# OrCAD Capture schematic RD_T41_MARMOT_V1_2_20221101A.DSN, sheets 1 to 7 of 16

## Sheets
1 PAGE01_COVER: title: RD_T41_MARMOT; rev: V1.2
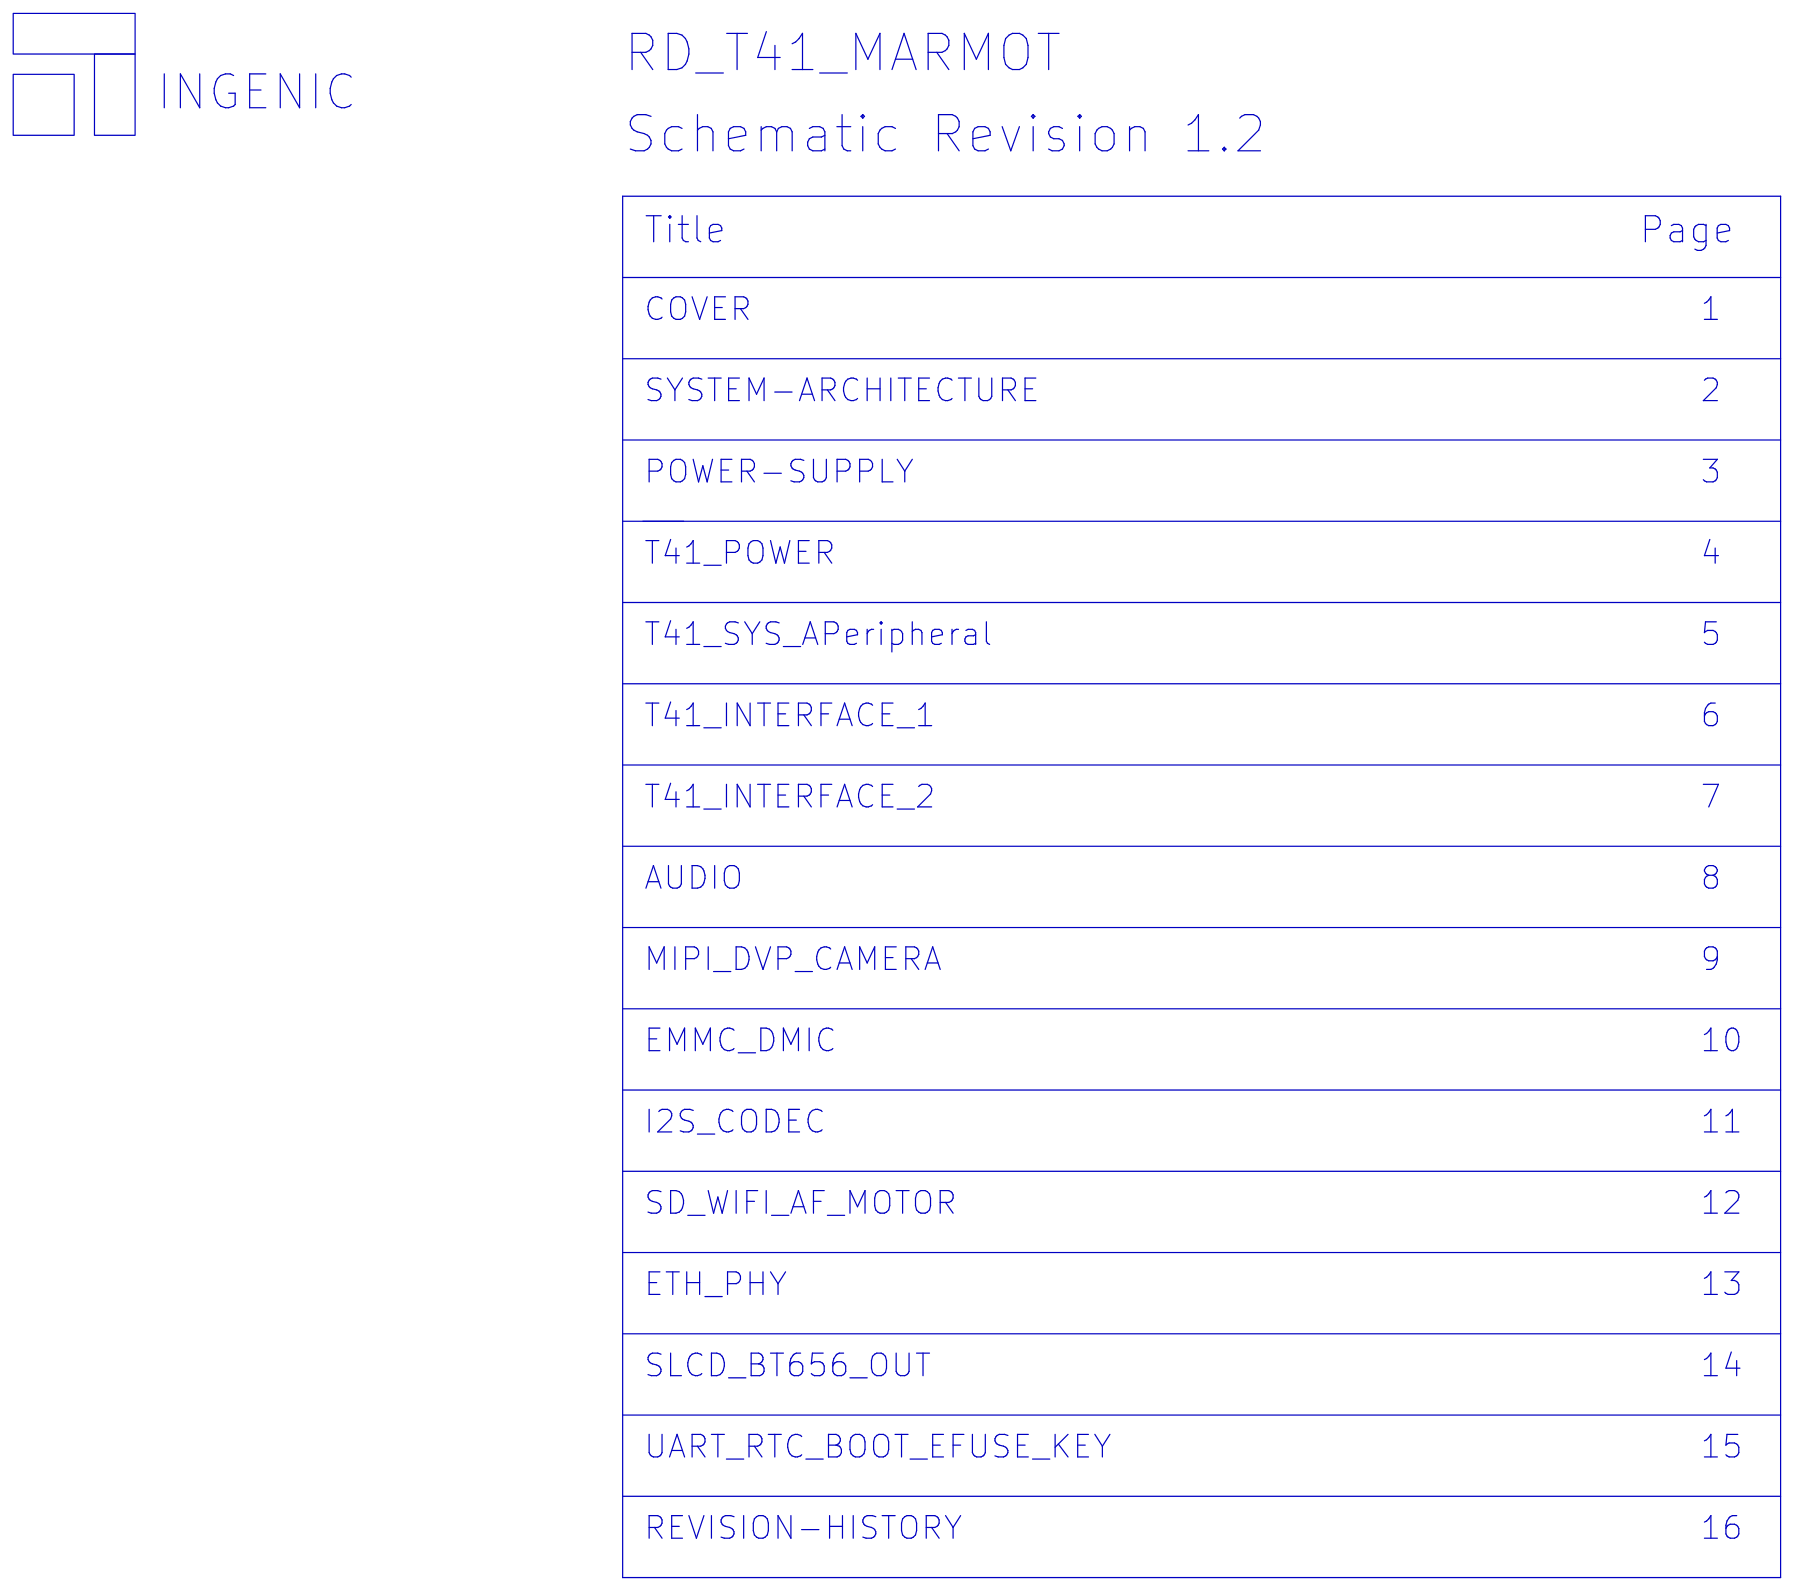
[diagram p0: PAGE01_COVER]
2 PAGE02_SYSTEM-ARCHITECT
3 PAGE03_POWER-SUPPLY: size A3
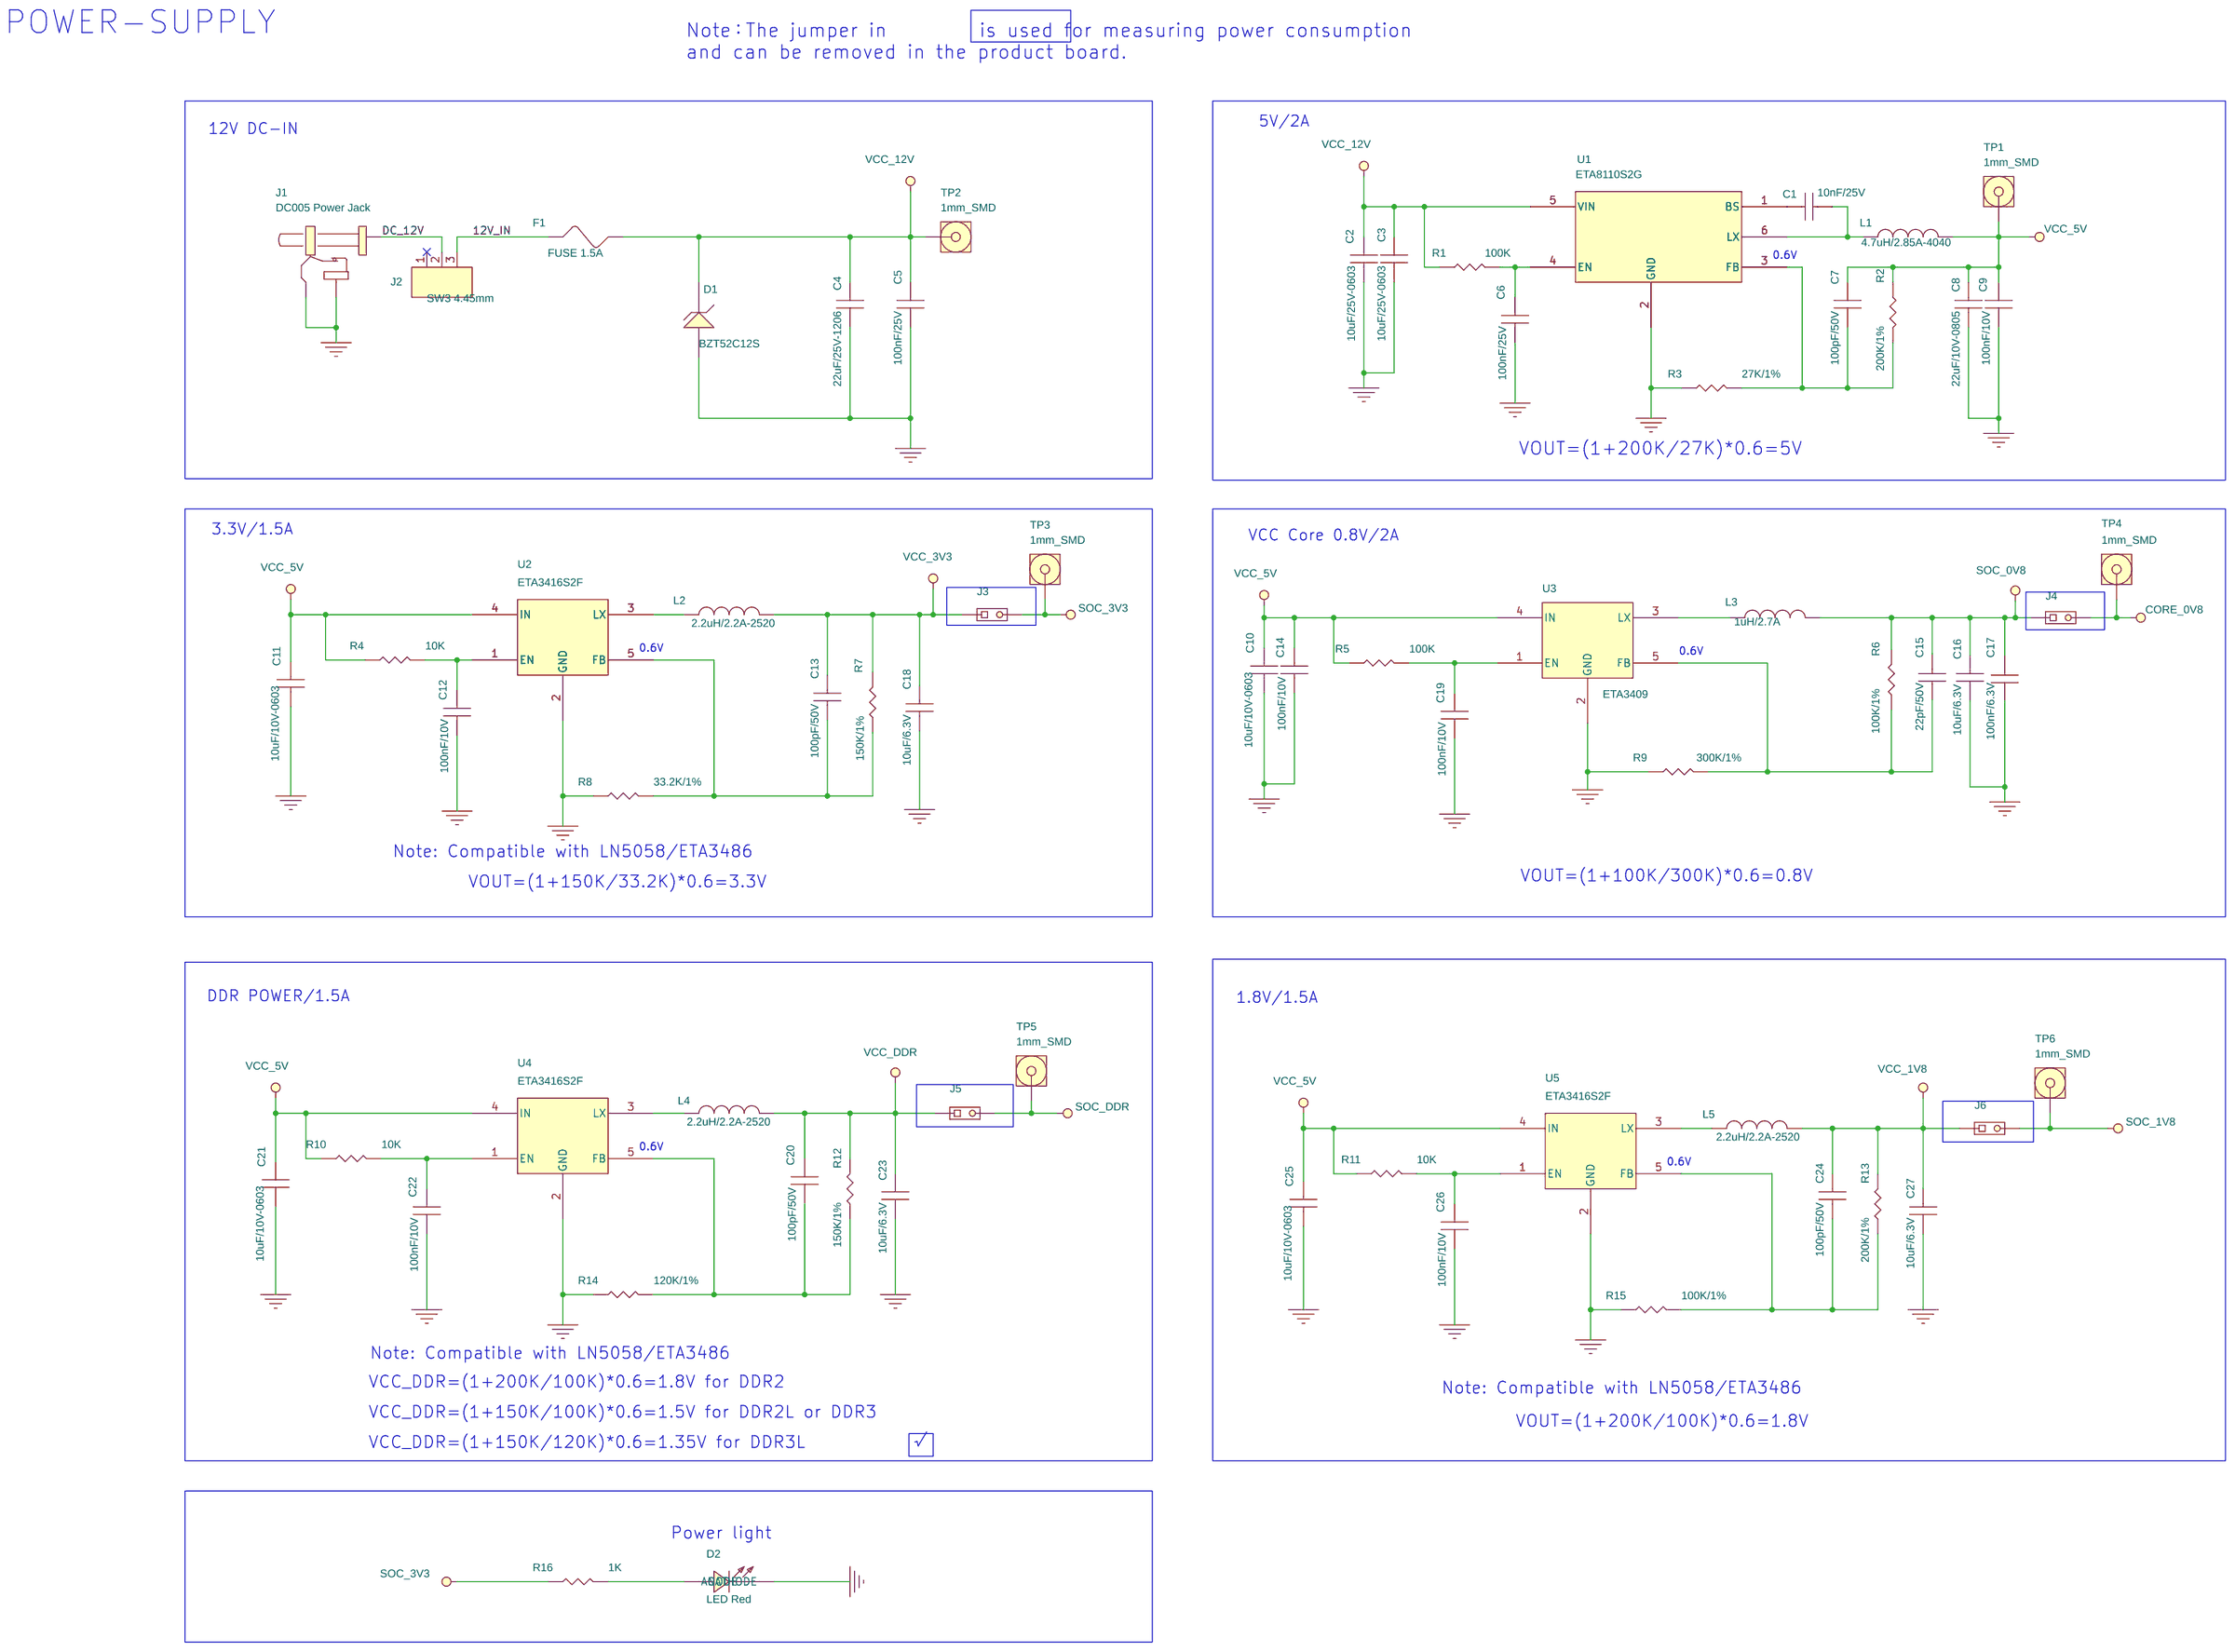
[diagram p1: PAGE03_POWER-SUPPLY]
4 PAGE04_T41_POWER: size A3
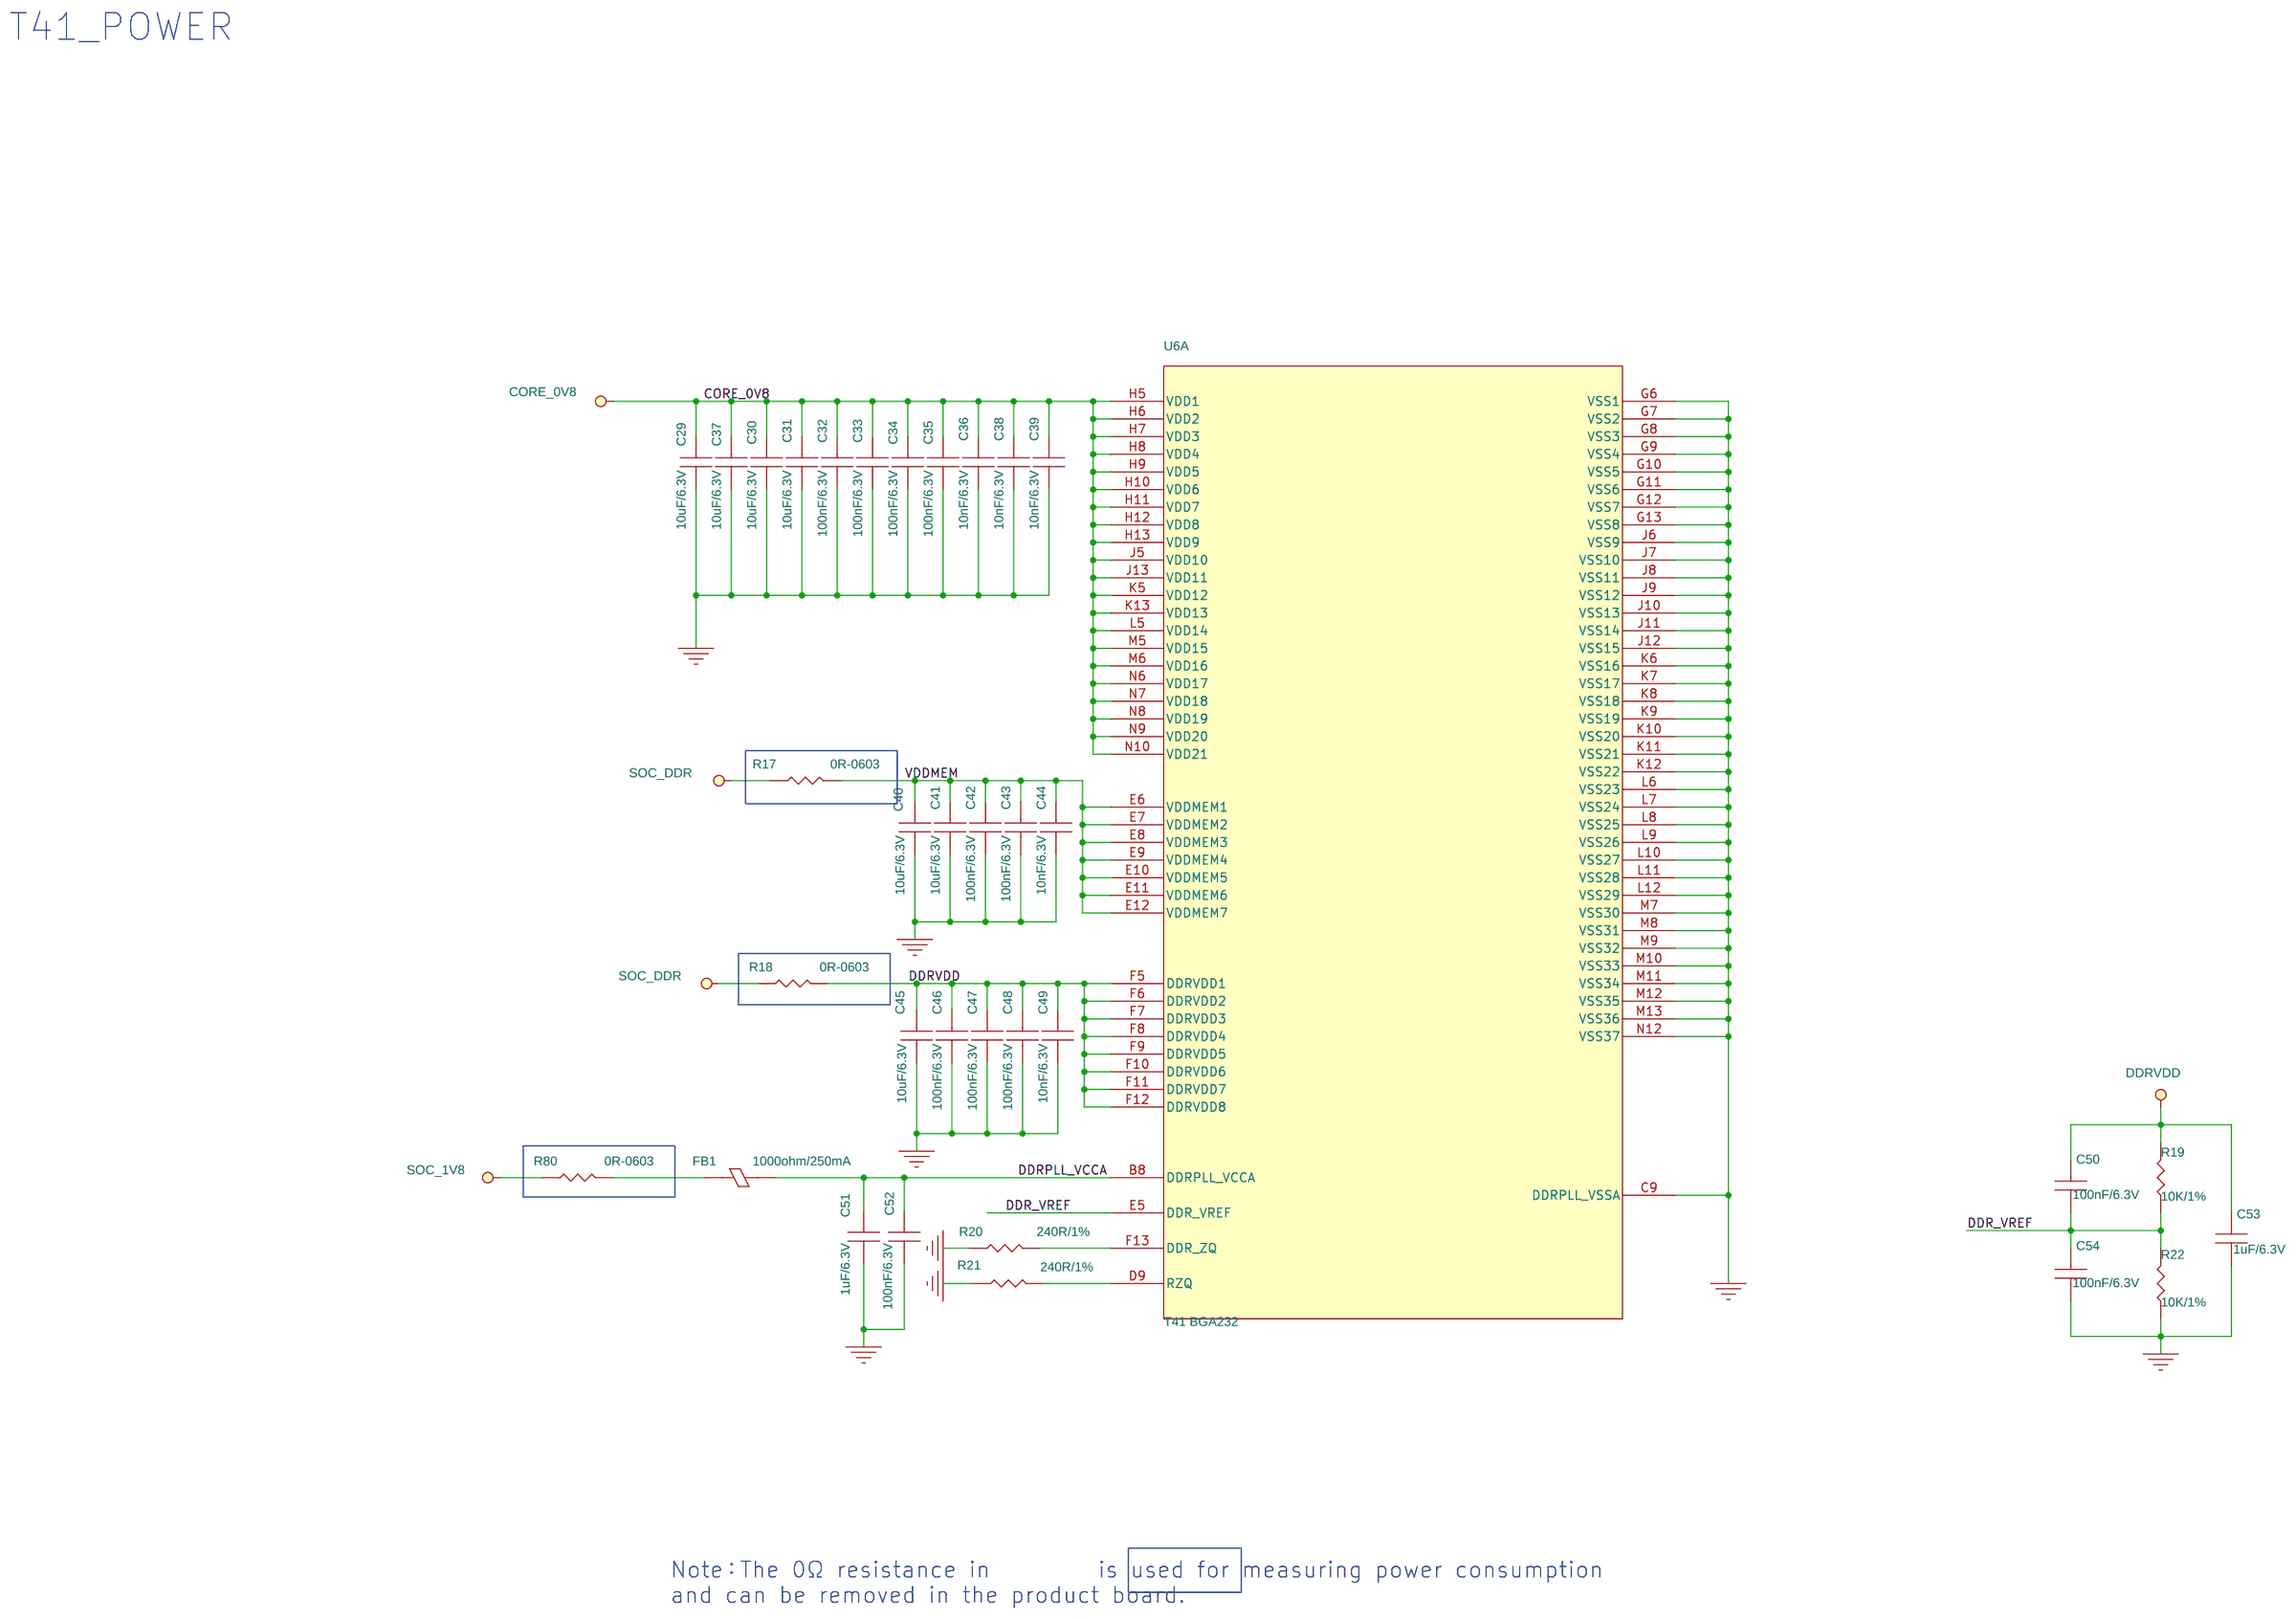
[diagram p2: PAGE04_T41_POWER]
5 PAGE05_T41_SYS_APeripheral: size A3
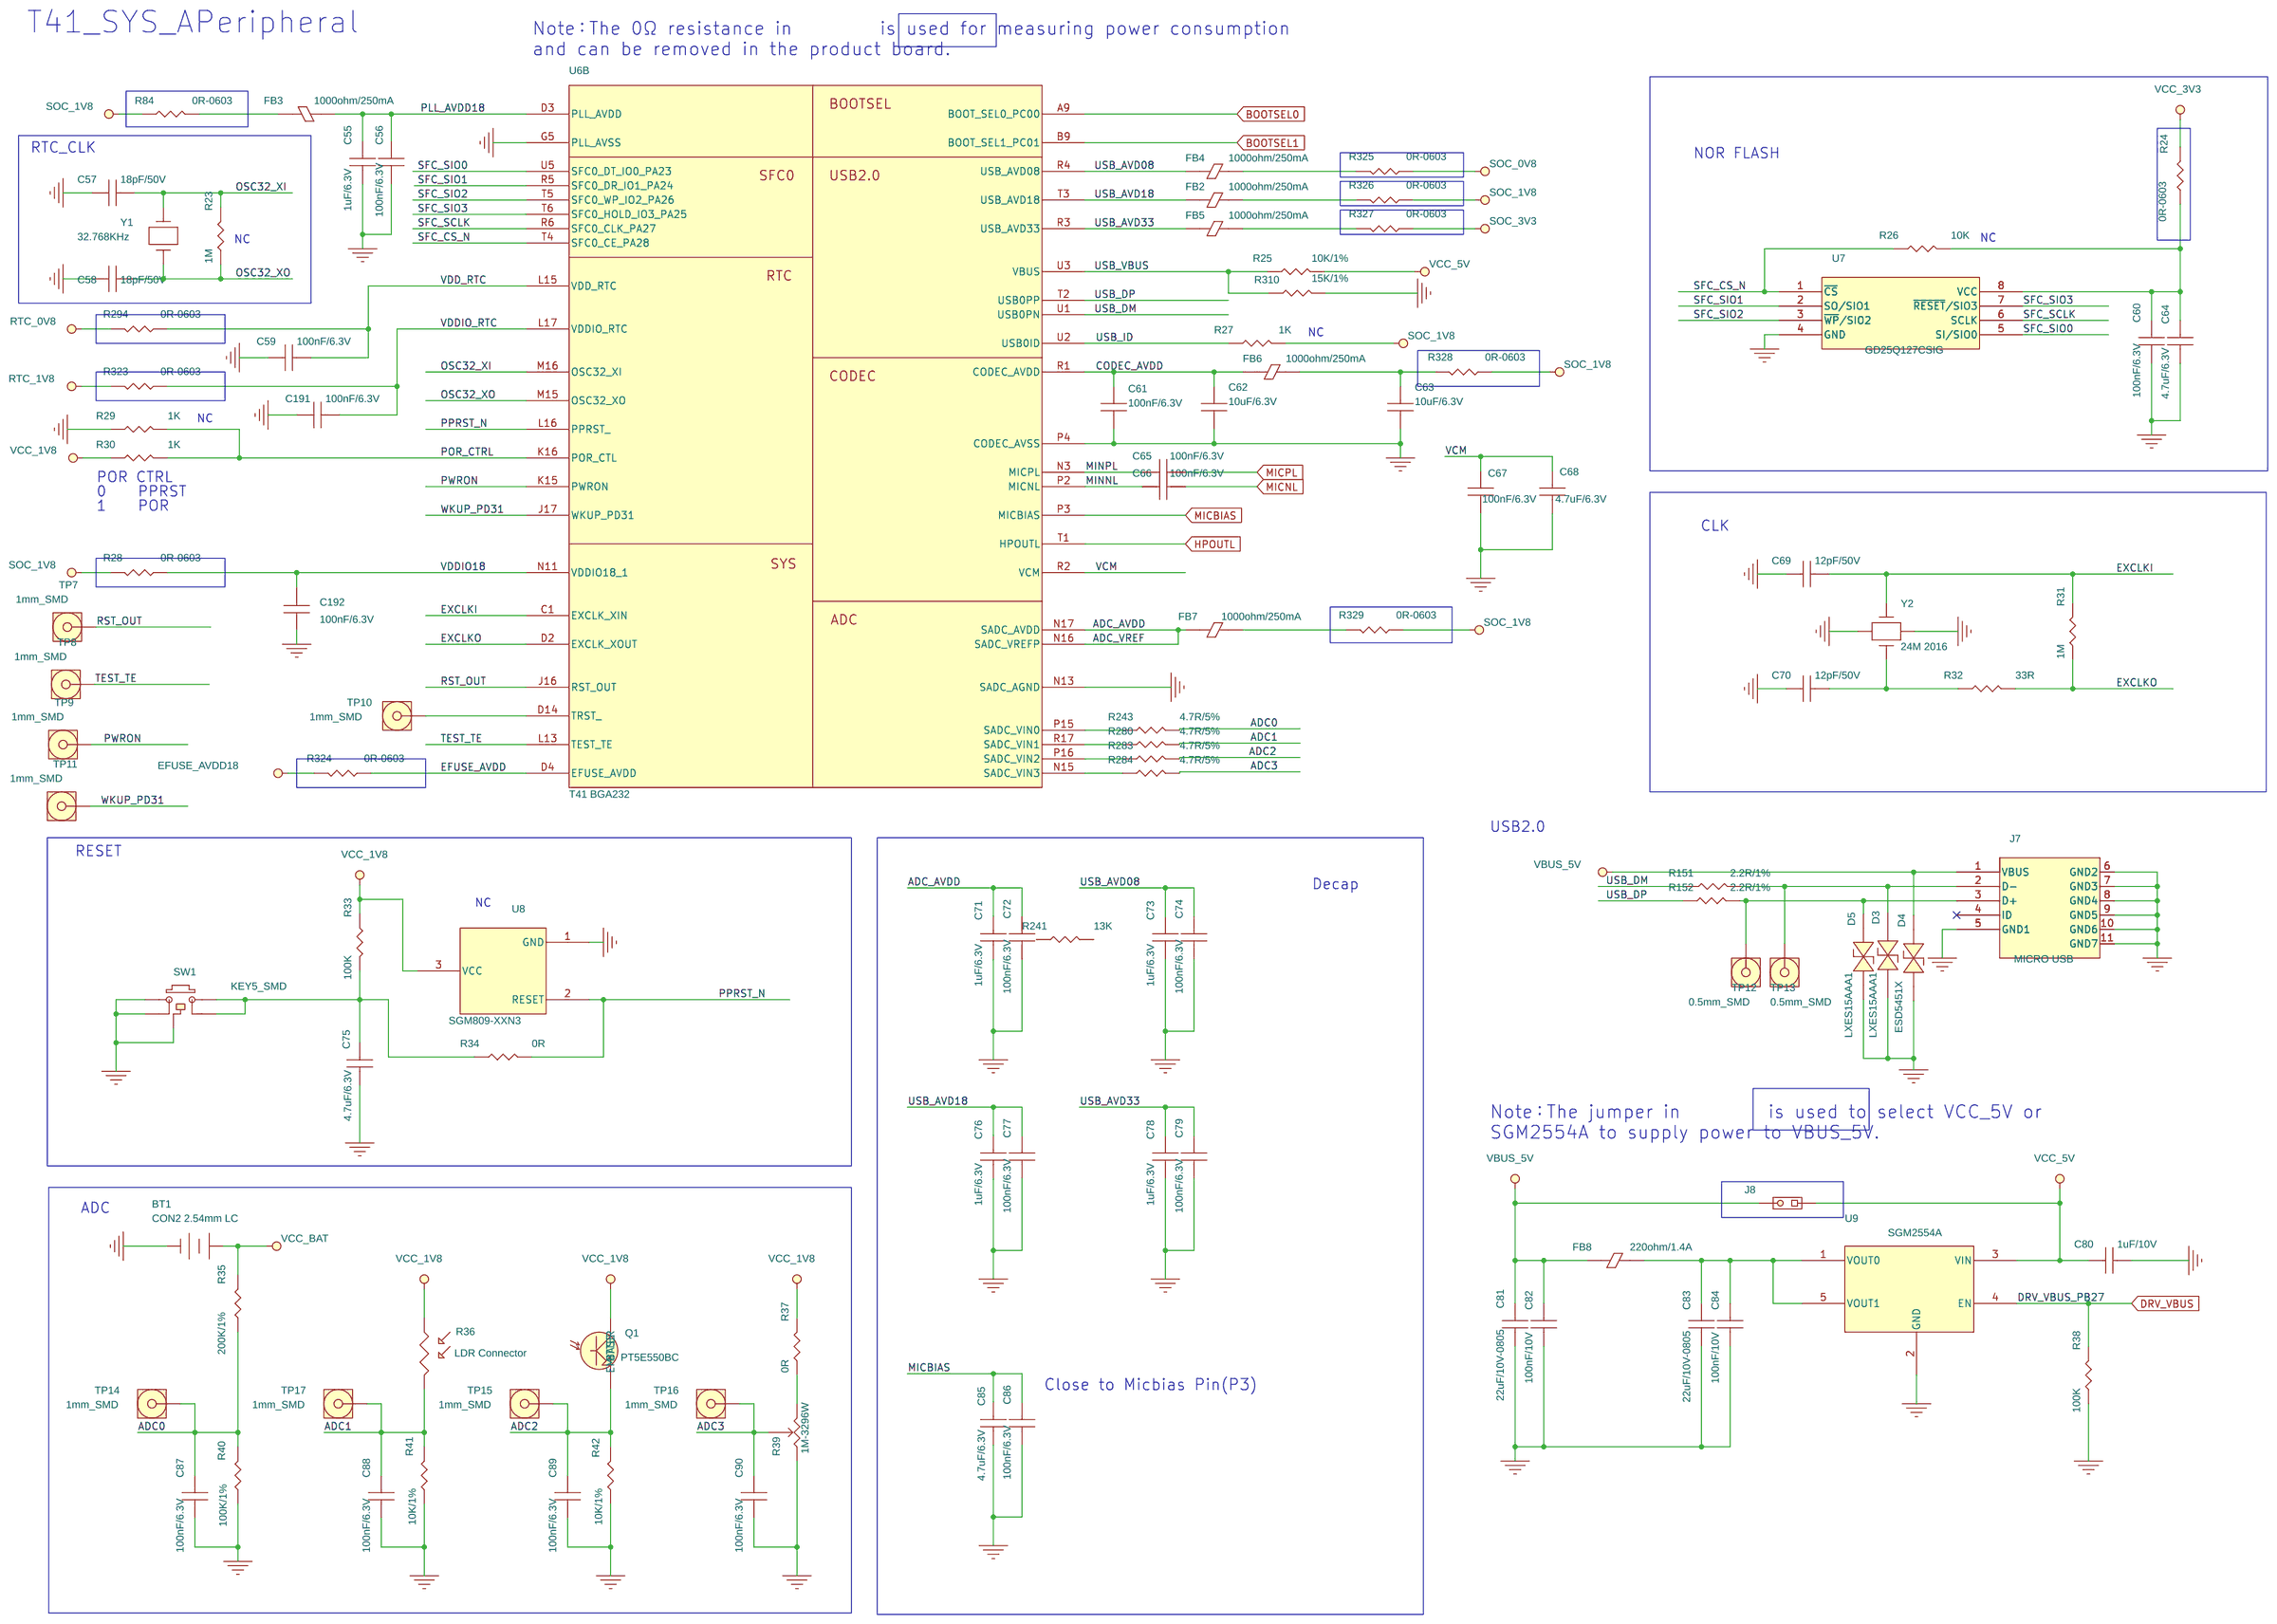
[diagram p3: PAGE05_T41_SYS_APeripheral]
6 PAGE06_T41_INTERFACE_P1: size A3
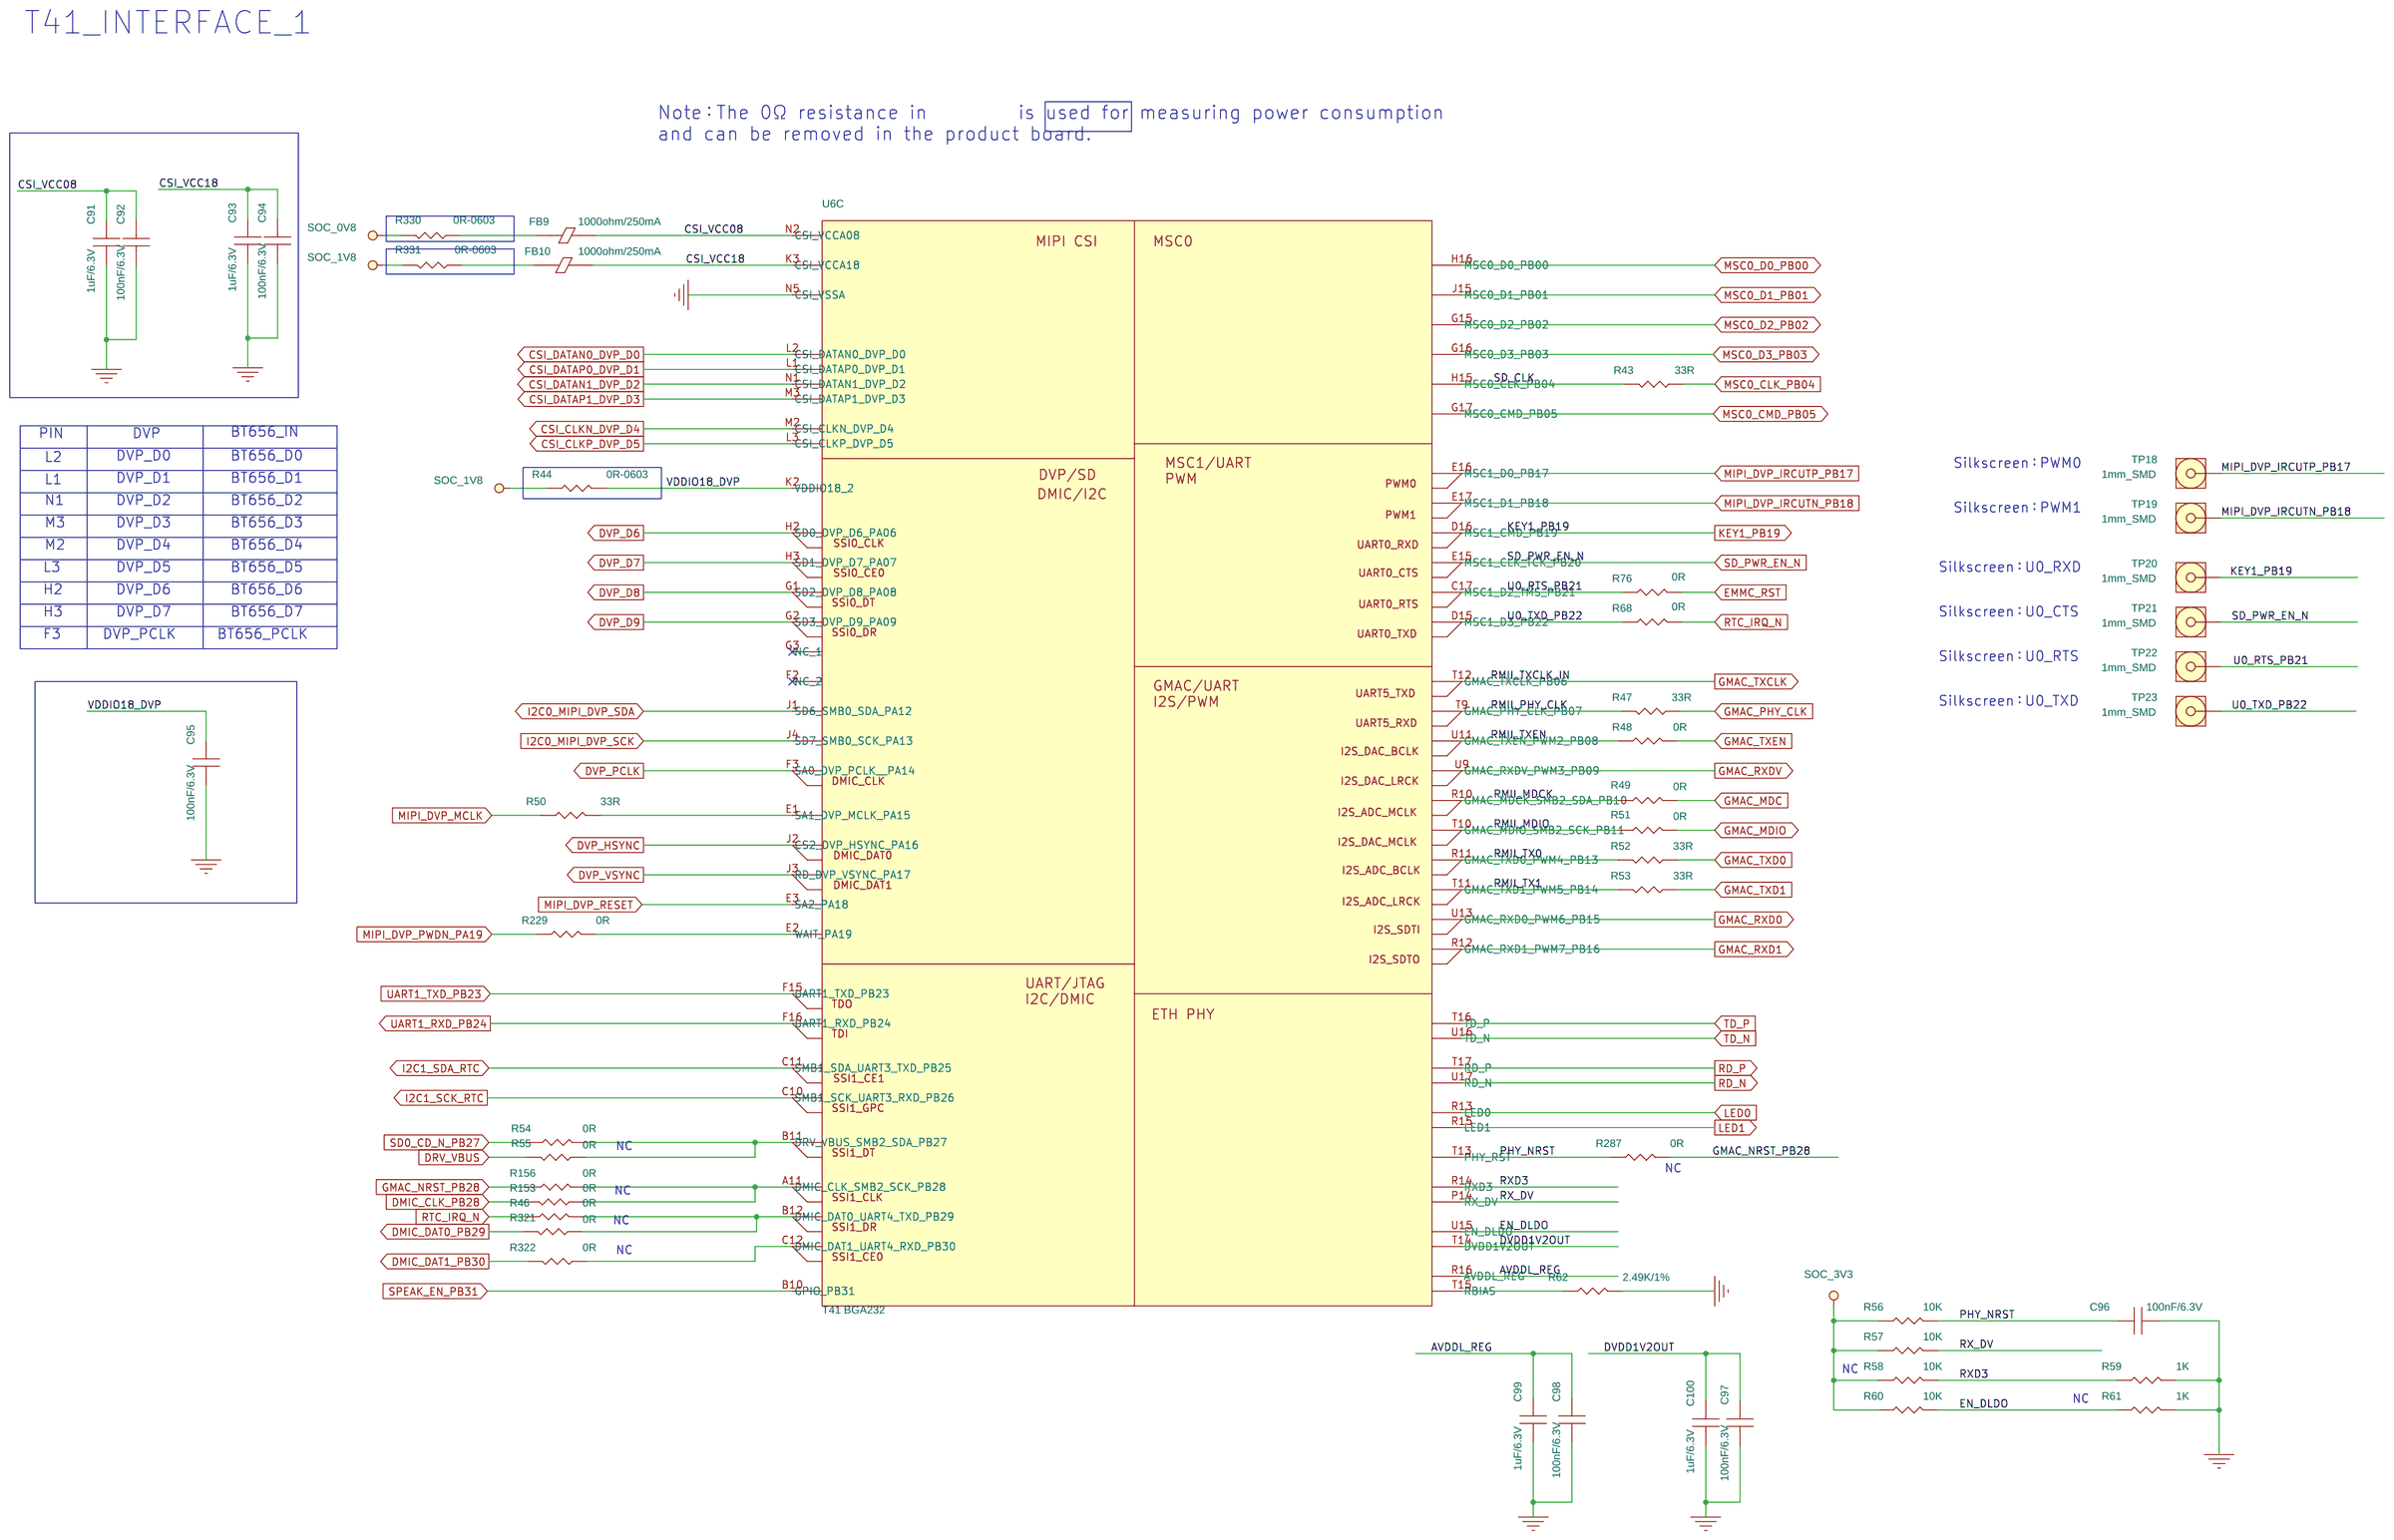
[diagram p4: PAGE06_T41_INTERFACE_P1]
7 PAGE07_T41_INTERFACE_P2: size A3
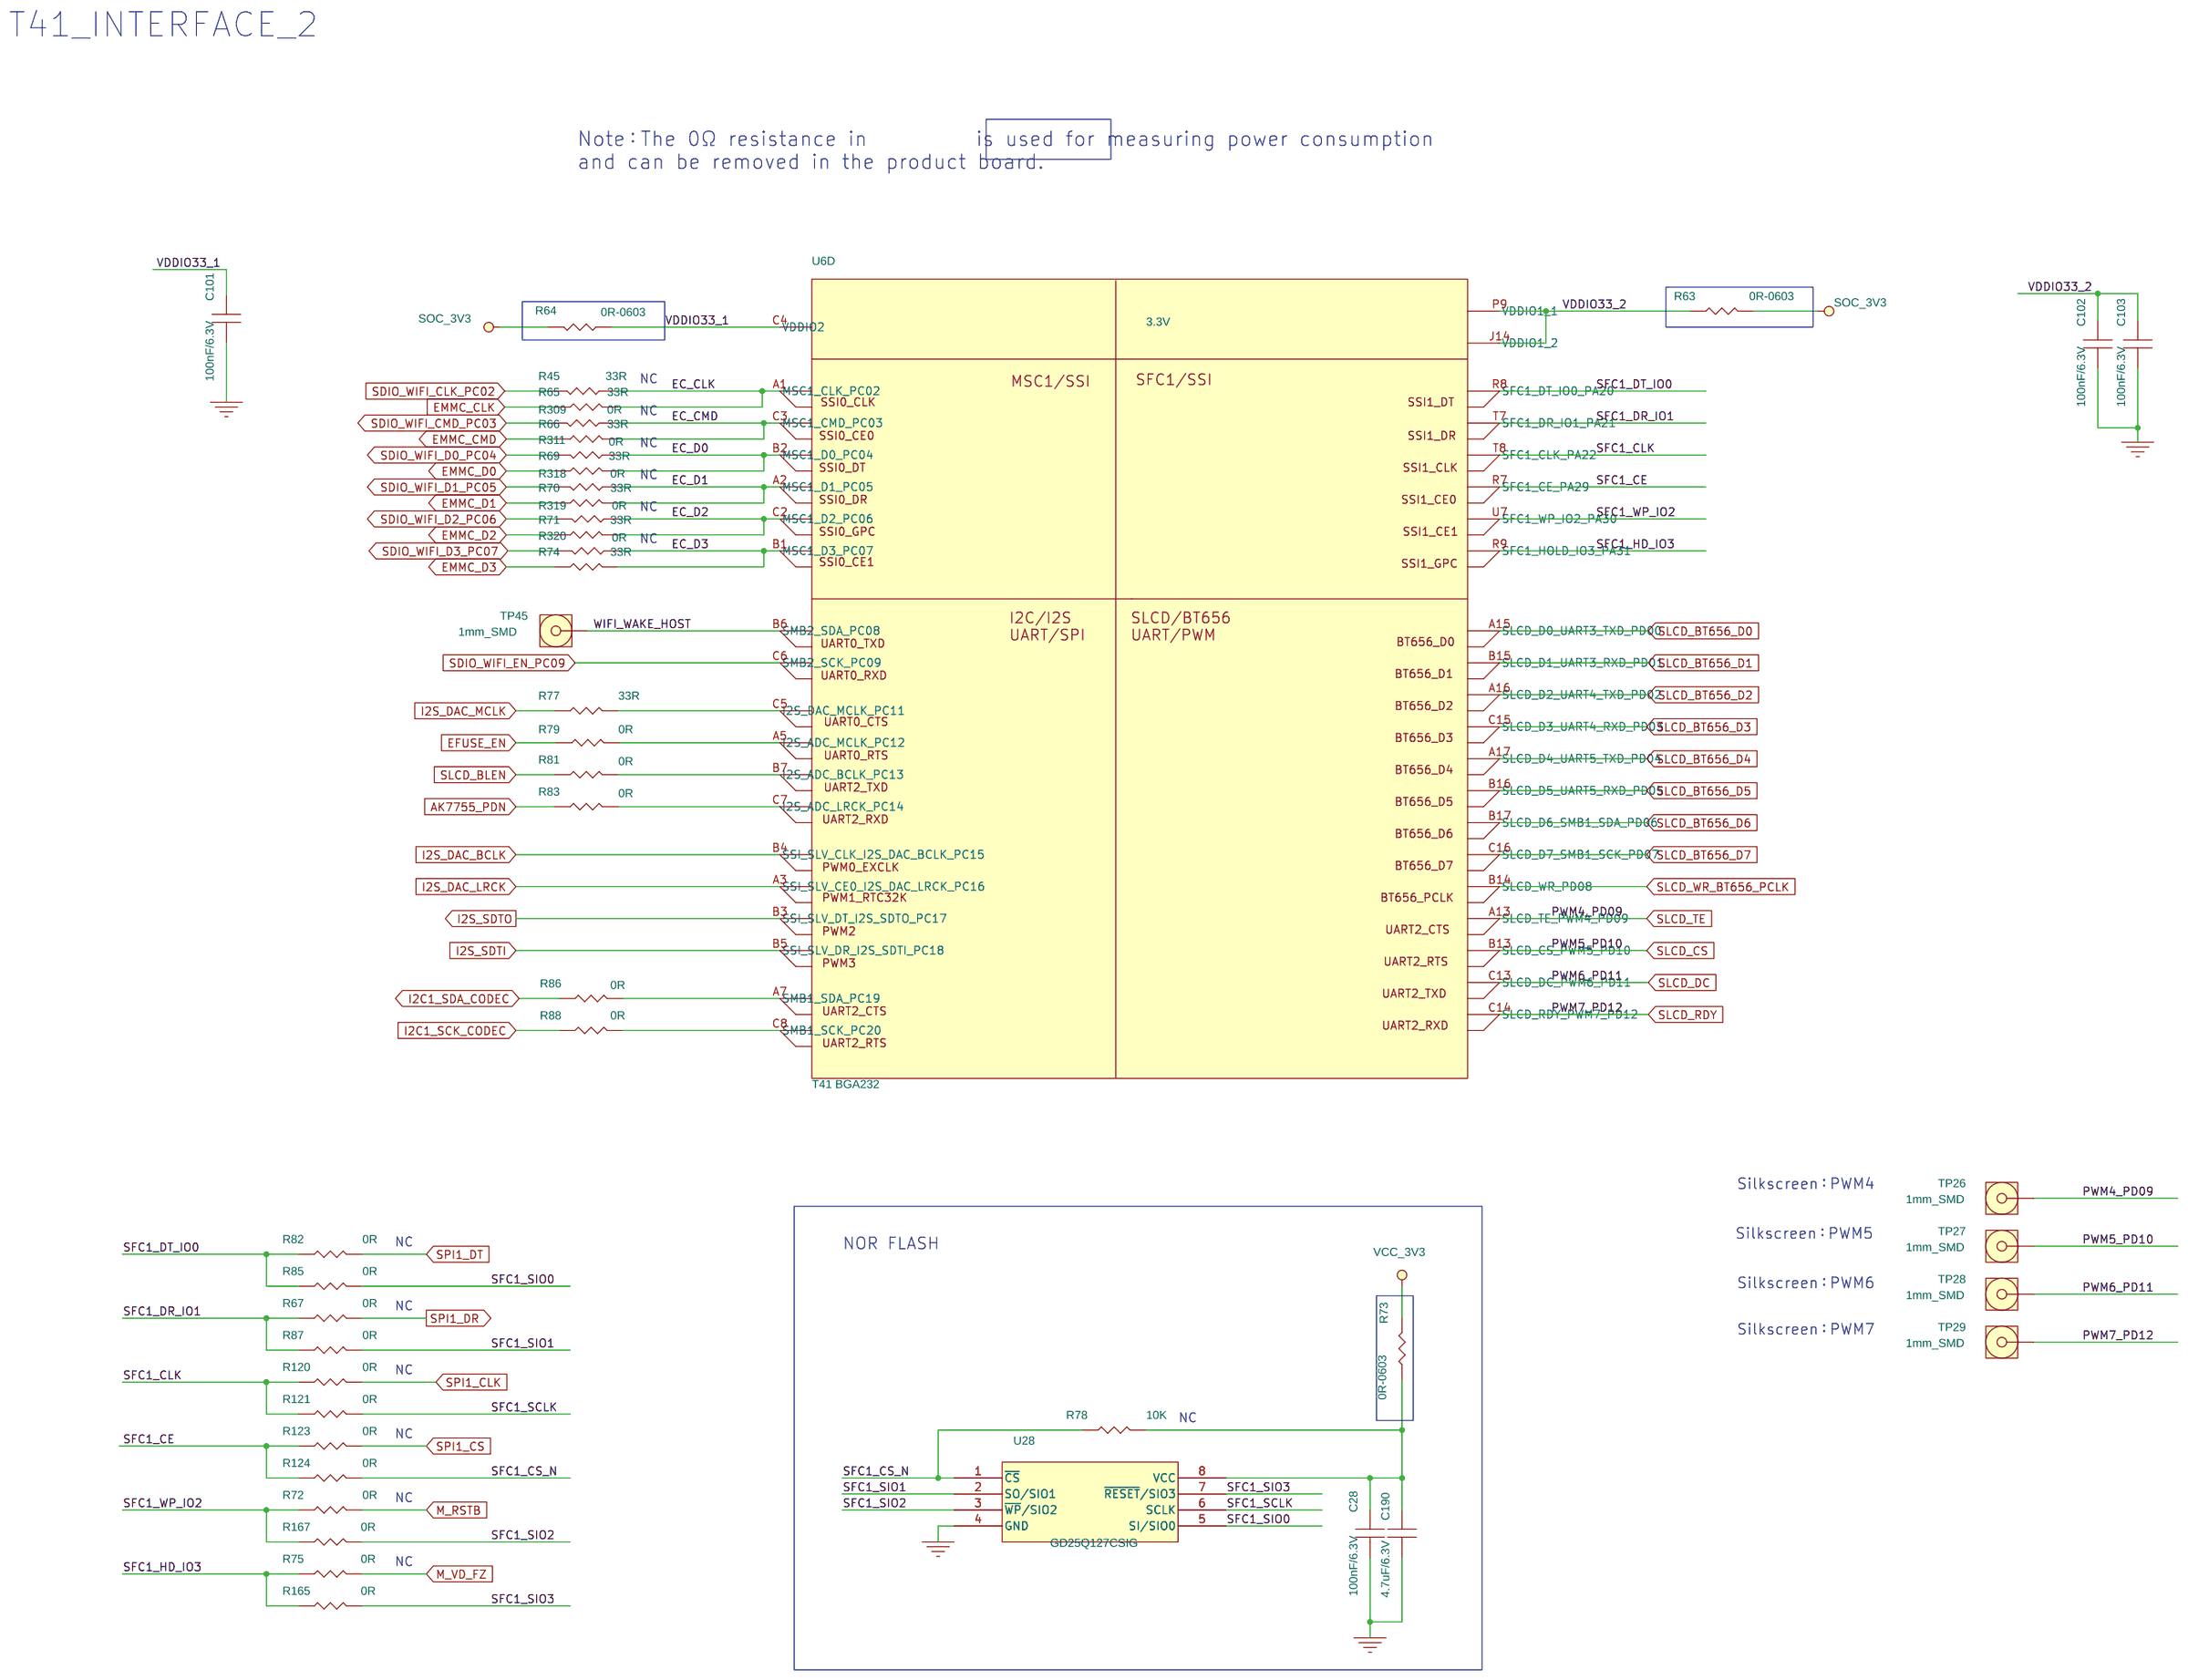
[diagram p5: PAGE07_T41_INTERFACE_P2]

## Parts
sheet PAGE03_POWER-SUPPLY
C1  10nF/25V  [C0402]
C2  10uF/25V-0603  [C0603]
C3  10uF/25V-0603  [C0603]
C4  22uF/25V-1206  [C1206]
C5  100nF/25V  [C0402]
C6  100nF/25V  [C0402]
C7  100pF/50V  [C0402]
C8  22uF/10V-0805  [C0805]
C9  100nF/10V  [C0402]
C10  10uF/10V-0603  [C0603]
C11  10uF/10V-0603  [C0603]
C12  100nF/10V  [C0402]
C13  100pF/50V  [C0402]
C14  100nF/10V  [C0402]
C15  22pF/50V  [C0402]
C16  10uF/6.3V  [C0402_E]
C17  100nF/6.3V  [C0402]
C18  10uF/6.3V  [C0402_E]
C19  100nF/10V  [C0402]
C20  100pF/50V  [C0402]
C21  10uF/10V-0603  [C0603]
C22  100nF/10V  [C0402]
C23  10uF/6.3V  [C0402_E]
C24  100pF/50V  [C0402]
C25  10uF/10V-0603  [C0603]
C26  100nF/10V  [C0402]
C27  10uF/6.3V  [C0402_E]
D1  BZT52C12S  [SOD323]
D2  LED Red  [D0603_LED]
F1  FUSE 1.5A  [F1812]
J1  DC005 Power Jack  [DC005]
J2  SW3 4.45mm  [PSW_3P]
J3  CON1X2_2.54P  [SIP2M_2D54]
J4  CON1X2_2.54P  [SIP2M_2D54]
J5  CON1X2_2.54P  [SIP2M_2D54]
J6  CON1X2_2.54P  [SIP2M_2D54]
L1  4.7uH/2.85A-4040  [L4040]
L2  2.2uH/2.2A-2520  [L2520]
L3  1uH/2.7A  [L2016]
L4  2.2uH/2.2A-2520  [L2520]
L5  2.2uH/2.2A-2520  [L2520]
R1  100K  [R0402]
R2  200K/1%  [R0402]
R3  27K/1%  [R0402]
R4  10K  [R0402]
R5  100K  [R0402]
R6  100K/1%  [R0402]
R7  150K/1%  [R0402]
R8  33.2K/1%  [R0402]
R9  300K/1%  [R0402]
R10  10K  [R0402]
R11  10K  [R0402]
R12  150K/1%  [R0402]
R13  200K/1%  [R0402]
R14  120K/1%  [R0402]
R15  100K/1%  [R0402]
R16  1K  [R0402]
TP1  1mm_SMD  [TEST_SMD]
TP2  1mm_SMD  [TEST_SMD]
TP3  1mm_SMD  [TEST_SMD]
TP4  1mm_SMD  [TEST_SMD]
TP5  1mm_SMD  [TEST_SMD]
TP6  1mm_SMD  [TEST_SMD]
U1  ETA8110S2G  [SOT23-6]
U2  ETA3416S2F  [SOT23-5]
U3  ETA3409  [SOT23-5]
U4  ETA3416S2F  [SOT23-5]
U5  ETA3416S2F  [SOT23-5]
sheet PAGE04_T41_POWER
C29  10uF/6.3V  [C0402_E]
C30  10uF/6.3V  [C0402_E]
C31  10uF/6.3V  [C0402_E]
C32  100nF/6.3V  [C0402]
C33  100nF/6.3V  [C0402]
C34  100nF/6.3V  [C0402]
C35  100nF/6.3V  [C0402]
C36  10nF/6.3V  [C0402]
C37  10uF/6.3V  [C0402_E]
C38  10nF/6.3V  [C0402]
C39  10nF/6.3V  [C0402]
C40  10uF/6.3V  [C0402_E]
C41  10uF/6.3V  [C0402_E]
C42  100nF/6.3V  [C0402]
C43  100nF/6.3V  [C0402]
C44  10nF/6.3V  [C0402]
C45  10uF/6.3V  [C0402_E]
C46  100nF/6.3V  [C0402]
C47  100nF/6.3V  [C0402]
C48  100nF/6.3V  [C0402]
C49  10nF/6.3V  [C0402]
C50  100nF/6.3V  [C0402]
C51  1uF/6.3V  [C0402]
C52  100nF/6.3V  [C0402]
C53  1uF/6.3V  [C0402]
C54  100nF/6.3V  [C0402]
FB1  1000ohm/250mA  [FB0402]
R17  0R-0603  [R0603]
R18  0R-0603  [R0603]
R19  10K/1%  [R0402]
R20  240R/1%  [R0402]
R21  240R/1%  [R0402]
R22  10K/1%  [R0402]
R80  0R-0603  [R0603]
sheet PAGE05_T41_SYS_APeripheral
BT1  CON2 2.54mm LC  [CON2-2D54-LC]
C55  1uF/6.3V  [C0402]
C56  100nF/6.3V  [C0402]
C57  18pF/50V  [C0402]
C58  18pF/50V  [C0402]
C59  100nF/6.3V  [C0402]
C60  100nF/6.3V  [C0402]
C61  100nF/6.3V  [C0402]
C62  10uF/6.3V  [C0402_E]
C63  10uF/6.3V  [C0402_E]
C64  4.7uF/6.3V  [C0402]
C65  100nF/6.3V  [C0402]
C66  100nF/6.3V  [C0402]
C67  100nF/6.3V  [C0402]
C68  4.7uF/6.3V  [C0402]
C69  12pF/50V  [C0402]
C70  12pF/50V  [C0402]
C71  1uF/6.3V  [C0402]
C72  100nF/6.3V  [C0402]
C73  1uF/6.3V  [C0402]
C74  100nF/6.3V  [C0402]
C75  4.7uF/6.3V  [C0402]
C76  1uF/6.3V  [C0402]
C77  100nF/6.3V  [C0402]
C78  1uF/6.3V  [C0402]
C79  100nF/6.3V  [C0402]
C80  1uF/10V  [C0402]
C81  22uF/10V-0805  [C0805]
C82  100nF/10V  [C0402]
C83  22uF/10V-0805  [C0805]
C84  100nF/10V  [C0402]
C85  4.7uF/6.3V  [C0402]
C86  100nF/6.3V  [C0402]
C87  100nF/6.3V  [C0402]
C88  100nF/6.3V  [C0402]
C89  100nF/6.3V  [C0402]
C90  100nF/6.3V  [C0402]
C191  100nF/6.3V  [C0402]
C192  100nF/6.3V  [C0402]
D3  LXES15AAA1  [R0402]
D4  ESD5451X  [ESD0402]
D5  LXES15AAA1  [R0402]
FB2  1000ohm/250mA  [FB0402]
FB3  1000ohm/250mA  [FB0402]
FB4  1000ohm/250mA  [FB0402]
FB5  1000ohm/250mA  [FB0402]
FB6  1000ohm/250mA  [FB0402]
FB7  1000ohm/250mA  [FB0402]
FB8  220ohm/1.4A  [FB0402]
J7  MICRO USB  [MICROUSB_B_NJ5P]
J8  CON1X2_2.54P  [SIP2M_2D54]
Q1  PT5E550BC  [PD2_2D54]
R23  1M  [R0402]
R24  0R-0603  [R0603]
R25  10K/1%  [R0402]
R26  10K  [R0402]
R27  1K  [R0402]
R28  0R-0603  [R0603]
R29  1K  [R0402]
R30  1K  [R0402]
R31  1M  [R0402]
R32  33R  [R0402]
R33  100K  [R0402]
R34  0R  [R0402]
R35  200K/1%  [R0402]
R36  LDR Connector  [SIP2M_2D54]
R37  0R  [R0402]
R38  100K  [R0402]
R39  1M-3296W  [VR_3296W]
R40  100K/1%  [R0402]
R41  10K/1%  [R0402]
R42  10K/1%  [R0402]
R84  0R-0603  [R0603]
R151  2.2R/1%  [R0402]
R152  2.2R/1%  [R0402]
R241  13K  [R0402]
R243  4.7R/5%  [R0402]
R280  4.7R/5%  [R0402]
R283  4.7R/5%  [R0402]
R284  4.7R/5%  [R0402]
R294  0R-0603  [R0603]
R310  15K/1%  [R0402]
R323  0R-0603  [R0603]
R324  0R-0603  [R0603]
R325  0R-0603  [R0603]
R326  0R-0603  [R0603]
R327  0R-0603  [R0603]
R328  0R-0603  [R0603]
R329  0R-0603  [R0603]
SW1  KEY5_SMD  [SW5_SMD]
TP7  1mm_SMD  [TEST_SMD]
TP8  1mm_SMD  [TEST_SMD]
TP9  1mm_SMD  [TEST_SMD]
TP10  1mm_SMD  [TEST_SMD]
TP11  1mm_SMD  [TEST_SMD]
TP12  0.5mm_SMD  [TEST_SMD_0D5]
TP13  0.5mm_SMD  [TEST_SMD_0D5]
TP14  1mm_SMD  [TEST_SMD]
TP15  1mm_SMD  [TEST_SMD]
TP16  1mm_SMD  [TEST_SMD]
TP17  1mm_SMD  [TEST_SMD]
U6  T41 BGA232  [BGA232_0D65_T41]  (sections A,B,C,D)
U7  GD25Q127CSIG  [WSOP8_1D27]
U8  SGM809-XXN3  [SOT23-3]
U9  SGM2554A  [SOT23-5]
Y1  32.768KHz  [CRY_3D2X1D5]
Y2  24M 2016  [CRY_2D5X2D0]
sheet PAGE06_T41_INTERFACE_P1
C91  1uF/6.3V  [C0402]
C92  100nF/6.3V  [C0402]
C93  1uF/6.3V  [C0402]
C94  100nF/6.3V  [C0402]
C95  100nF/6.3V  [C0402]
C96  100nF/6.3V  [C0402]
C97  100nF/6.3V  [C0402]
C98  100nF/6.3V  [C0402]
C99  1uF/6.3V  [C0402]
C100  1uF/6.3V  [C0402]
FB9  1000ohm/250mA  [FB0402]
FB10  1000ohm/250mA  [FB0402]
R43  33R  [R0402]
R44  0R-0603  [R0603]
R46  0R  [R0402]
R47  33R  [R0402]
R48  0R  [R0402]
R49  0R  [R0402]
R50  33R  [R0402]
R51  0R  [R0402]
R52  33R  [R0402]
R53  33R  [R0402]
R54  0R  [R0402]
R55  0R  [R0402]
R56  10K  [R0402]
R57  10K  [R0402]
R58  10K  [R0402]
R59  1K  [R0402]
R60  10K  [R0402]
R61  1K  [R0402]
R62  2.49K/1%  [R0402]
R68  0R  [R0402]
R76  0R  [R0402]
R153  0R  [R0402]
R156  0R  [R0402]
R229  0R  [R0402]
R287  0R  [R0402]
R321  0R  [R0402]
R322  0R  [R0402]
R330  0R-0603  [R0603]
R331  0R-0603  [R0603]
TP18  1mm_SMD  [TEST_SMD]
TP19  1mm_SMD  [TEST_SMD]
TP20  1mm_SMD  [TEST_SMD]
TP21  1mm_SMD  [TEST_SMD]
TP22  1mm_SMD  [TEST_SMD]
TP23  1mm_SMD  [TEST_SMD]
sheet PAGE07_T41_INTERFACE_P2
C28  100nF/6.3V  [C0402]
C101  100nF/6.3V  [C0402]
C102  100nF/6.3V  [C0402]
C103  100nF/6.3V  [C0402]
C190  4.7uF/6.3V  [C0402]
R45  33R  [R0402]
R63  0R-0603  [R0603]
R64  0R-0603  [R0603]
R65  33R  [R0402]
R66  33R  [R0402]
R67  0R  [R0402]
R69  33R  [R0402]
R70  33R  [R0402]
R71  33R  [R0402]
R72  0R  [R0402]
R73  0R-0603  [R0603]
R74  33R  [R0402]
R75  0R  [R0402]
R77  33R  [R0402]
R78  10K  [R0402]
R79  0R  [R0402]
R81  0R  [R0402]
R82  0R  [R0402]
R83  0R  [R0402]
R85  0R  [R0402]
R86  0R  [R0402]
R87  0R  [R0402]
R88  0R  [R0402]
R120  0R  [R0402]
R121  0R  [R0402]
R123  0R  [R0402]
R124  0R  [R0402]
R165  0R  [R0402]
R167  0R  [R0402]
R309  0R  [R0402]
R311  0R  [R0402]
R318  0R  [R0402]
R319  0R  [R0402]
R320  0R  [R0402]
TP26  1mm_SMD  [TEST_SMD]
TP27  1mm_SMD  [TEST_SMD]
TP28  1mm_SMD  [TEST_SMD]
TP29  1mm_SMD  [TEST_SMD]
TP45  1mm_SMD  [TEST_SMD]
U28  GD25Q127CSIG  [WSOP8_1D27]

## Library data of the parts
C1 = CAP: Capacitor-10nF,+/-10%,X7R,25V-0402; Part Number: 02.0012.00; Part Type: 0402表贴普通电容; 供应商: 国巨 / Murata; 规格型号1: CC0402KRX7R8BB103 / GCM155R71E103KA37D; 联系人: 谢苏云; 手机: 15900554174; 邮箱: susan.xie@murata.com
C2 C3 = CAP: Capacitor-10uF,+/-20%,X5R,25V-0603; Part Number: 02.0027.00; Part Type: 0603表贴普通电容; 供应商: Murata; 规格型号1: GRM188R61E106MA73D; 联系人: 谢苏云; 手机: 15900554174; 邮箱: susan.xie@murata.com
C4 = CAP: Capacitor-22uF,+/-10%,X5R,25V-1206; Part Number: 02.0032.00; Part Type: 1206表贴普通电容; 供应商: 华新科 / Murata; 供应商1: Eyang; 规格型号1: 1206X226K250CT / GRM31CR61E226KE15L; 联系人: 谢苏云; 联系人1: 何俊; 手机: 15900554174; 手机1: 18317187178; 邮箱: susan.xie@murata.com; 邮箱1: hejunxs@szeyang.com
C5 = CAP: Capacitor-100nF,+/-10%,X5R,25V-0402; Part Number: 02.0038.00; Part Type: 0402表贴普通电容; 供应商: 国巨 / Murata; 供应商1: Eyang; 规格型号1: CC0402KRX5R8BB104 / GRM155R71E104KE14D; 联系人: 谢苏云; 联系人1: 何俊; 手机: 15900554174; 手机1: 18317187178; 邮箱: susan.xie@murata.com; 邮箱1: hejunxs@szeyang.com
C6 = CAP: Capacitor-100nF,+/-10%,X5R,25V-0402; Part Number: 02.0038.00; Part Type: 0402表贴普通电容; 供应商: 国巨 / Murata; 规格型号1: CC0402KRX5R8BB104 / GRM155R71E104KE14D; 联系人: 谢苏云; 手机: 15900554174; 邮箱: susan.xie@murata.com
C7 = CAP: Capacitor-100pF,+/-5%,C0G,50V-0402; Part Number: 02.0059.00; Part Type: 0402表贴普通电容; 供应商: 国巨 / Murata; 规格型号1: CC0402JRNPO9BN101 / GCM1555C1H101JA16D; 联系人: 谢苏云; 手机: 15900554174; 邮箱: susan.xie@murata.com
C8 C81 C83 = CAP: Capacitor-22uF,+/-20%,X5R,10V-0805; Part Number: 02.0076.00; Part Type: 0805表贴普通电容; 供应商: 华新科 / Murata; 规格型号1: 0805X226M100CT / GRM21BR61A226ME51L; 联系人: 谢苏云; 手机: 15900554174; 邮箱: susan.xie@murata.com
C9 C12 C14 C19 C22 C26 C82 C84 = CAP: Capacitor-100nF,+/-10%,X7R,10V-0402; Part Number: 02.0075.00; Part Type: 0402表贴普通电容; 供应商: Murata; 供应商1: Eyang; 规格型号1: GRM155R71A104KA01D; 联系人: 谢苏云; 联系人1: 何俊; 手机: 15900554174; 手机1: 18317187178; 邮箱: susan.xie@murata.com; 邮箱1: hejunxs@szeyang.com
C10 C11 C21 C25 = CAP: Capacitor-10uF,+/-20%,X5R,10V-0603; Part Number: 02.0026.00; Part Type: 0603表贴普通电容; 供应商: YAGEO / Murata; 规格型号1: CC0603MRX5R6BB106 / GRM188R61A106KE47D; 联系人: 谢苏云; 手机: 15900554174; 邮箱: susan.xie@murata.com
C13 C20 C24 = CAP: Capacitor-100pF,+/-5%,C0G,50V-0402; Part Number: 02.0059.00; Part Type: 0402表贴普通电容; 供应商: 国巨 / Murata; 供应商2: Murata; 规格型号1: CC0402JRNPO9BN101 / GCM1555C1H101JA16D; 联系人: 谢苏云; 联系人2: 吴铭; 手机: 15900554174; 手机2: 13761466262; 邮箱: susan.xie@murata.com; 邮箱2: cherry.wu@murata.com
C15 = CAP: Capacitor-22pF,+/-5%,C0G,50V-0402; Part Number: 02.0008.00; Part Type: 0402表贴普通电容; 供应商: YAGEO / Murata; 规格型号1: CC0402JRNPO9BN220 / GRM1552C1H220JA01D; 联系人: 谢苏云; 手机: 15900554174; 邮箱: susan.xie@murata.com
C16 = CAP: Capacitor-10uF,+/-20%,X5R,6.3V-0402+; Part Number: 02.0034.00; Part Type: 0402表贴普通电容; 供应商: YAGEO / Murata; 供应商2: Murata; 规格型号1: CC0402MRX5R5BB106 / GRM155R60J106ME44D; 联系人: 谢苏云; 联系人2: 吴铭; 手机: 15900554174; 手机2: 13761466262; 邮箱: susan.xie@murata.com; 邮箱2: cherry.wu@murata.com
C17 C28 C32-C35 C42 C43 C46-C48 C50 C52 C54 C56 C59-C61 C65-C67 C72 C74 C77 C79 C86-C90 C92 C94-C98 C101-C103 C191 C192 = CAP: Capacitor-100nF,+/-10%,X7R,6.3V-0402; Part Number: 02.0075.00; Part Type: 0402表贴普通电容; 供应商: Murata; 规格型号1: GRM155R70J104KA01D; 联系人: 谢苏云; 手机: 15900554174; 邮箱: susan.xie@murata.com
C18 C23 C27 = CAP: Capacitor-10uF,+/-20%,X5R,6.3V-0402+; Part Number: 02.0034.00; Part Type: 0402表贴普通电容; 供应商: 国巨 / Murata; 供应商2: Murata; 规格型号1: CC0402MRX5R5BB106 / GRM155R60J106ME44D; 联系人: 谢苏云; 联系人2: 吴铭; 手机: 15900554174; 手机2: 13761466262; 邮箱: susan.xie@murata.com; 邮箱2: cherry.wu@murata.com
D1 = DIODE_WY: CHANGJIANG ELECTRONICS BZT52C12S  ZENER DIODE; Part Number: 09.0002.00; Part Type: 稳压二极管
D2 = LED_1: Part Number: 09.0003.00; Part Type: 发光二极管; 规格型号1: 0603贴片红灯; Datasheet: 0603_LED.PDF
F1 = FUSE: Resettable Fuse 1.5A 1812; Part Number: 10.0010.00; Part Type: 保险丝; 规格型号1: 1812 1.5A保险丝
J1 = DC_005: Wieson WS-DC-005ASNT1 Power Jack; Part Number: 10.0004.00; Part Type: Power Jack; 规格型号1: WS-DC-005ASNT1; Datasheet: DC-0005.pdf
J2 = SW3: POWER SWITCH 3Pin 4.45mm Pitch; Part Number: 04.2001.00; Part Type: 拨动开关; 规格型号1: SS12D10
J3-J6 J8 = HEADER2x1_A: HEADER 2X1 2.54mm MALE; Part Number: 04.0031.01; Part Type: 2.54mm单排插针; 规格型号1: 2.54mm 1X2单排插针
L1 = INDUCTOR: Sunlord WPN4020H4R7MT 4.7uH/2.85A-4040 POWER INDUCTOR; Part Number: 03.0016.00; Part Type: 4040表贴电感; 供应商: Sunlord; 规格型号1: WPN4020H4R7MT; 联系人: 张永泉; 手机: 13823223481; 邮箱: yongquan_zhang@sunlordinc.com; Datasheet: WPN+series+of+SMD+Power+Inductor.pdf
L2 L4 L5 = INDUCTOR: MuRata DFE252012P-2R2MS=P2 2.2uH/2.2A-2520 POWER INDUCTOR; Part Number: 03.0021.00; Part Type: 2520表贴电感; 供应商: Murata; 规格型号1: DFE252012P-2R2MS=P2; 联系人: 谢苏云; 手机: 15900554174; 邮箱: susan.xie@murata.com; Datasheet: DFE252012P_Murata data sheet150828.pdf
L3 = INDUCTOR: Murata DFE201612P-1R0M=P2 1uH/2.7A（Tr=40）±20% H=1.2mm POWER INDUCTOR; Part Number: 03.0035.00; Part Type: 2016表贴电感; 供应商: Murata; 规格型号1: DFE201612P-1R0M=P2; 联系人: 谢苏云; 手机: 15900554174; 邮箱: susan.xie@murata.com; Datasheet: DFE201612P_Murata data sheet_170130.pdf
R1 R5 R33 R38 = RES: Resistor-100K,+/-5%,1/16W-0402; Part Number: 01.0041.00; Part Type: 0402表贴普通电阻; 供应商: 厚声; 规格型号1: 0402WGJ0104TCE
R2 R13 R35 = RES: Resistor-200K,+/-1%,1/16W-0402; Part Number: 01.0045.00; Part Type: 0402表贴高精度电阻; 供应商: 厚声; 规格型号1: 0402WGF2003TCE
R3 = RES: Resistor-27K,+/-1%,1/16W-0402; Part Number: 01.0029.00; Part Type: 0402表贴高精度电阻; 供应商: 厚声; 规格型号1: 0402WGF2702TCE
R4 R10 R11 R26 R56-R58 R60 R78 = RES: Resistor-10K,+/-5%,1/16W-0402; Part Number: 01.0023.00; Part Type: 0402表贴普通电阻; 供应商: 厚声; 规格型号1: 0402WGJ0103TCE
R6 R15 R40 = RES: Resistor-100K,+/-1%,1/16W-0402; Part Number: 01.0040.00; Part Type: 0402表贴高精度电阻; 供应商: 厚声; 规格型号1: 0402WGF1003TCE
R7 R12 = RES: Resistor-150K,+/-1%,1/16W-0402; Part Number: 01.0043.00; Part Type: 0402表贴高精度电阻; 供应商: 厚声; 规格型号1: 0402WGF1503TCE
R8 = RES: Resistor-33.2K,+/-1%,1/16W-0402; Part Number: 01.0032.00; Part Type: 0402表贴高精度电阻; 供应商: 厚声; 规格型号1: 0402WGF3322TCE
R9 = RES: Resistor-300K,+/-1%,1/16W-0402; Part Number: 01.0046.00; Part Type: 0402表贴高精度电阻; 供应商: 厚声; 规格型号1: 0402WGF3003TCE
R14 = RES: Resistor-120K,+/-1%,1/16W-0402; Part Number: 01.0042.00; Part Type: 0402表贴高精度电阻; 供应商: 厚声; 规格型号1: 0402WGF1203TCE
R16 R27 R29 R30 R59 R61 = RES: Resistor-1K,+/-5%,1/16W-0402; Part Number: 01.0014.00; Part Type: 0402表贴普通电阻; 供应商: 厚声; 规格型号1: 0402WGJ0102TCE
TP1-TP11 TP14-TP23 TP26-TP29 TP45 = TP: SMD Test Point φ1mm; Part Number: AA.0001.00; Part Type: Test Point
U1 = ETA8110: ETA ETA8110 2A 1MHz Input-3.5V~24V Buck Regulator; Part Number: 05.2031.00; Part Type: 降压型DCDC; 供应商: ETA; 联系人: 徐卓荣; 手机: 13923780263; 邮箱: xuzhuorong@etasolution.com; Datasheet: ETA8110 V1.0.pdf
U2 U4 U5 = ETA3416: ETA ETA3416 1.5A 3MHz Input-2.6V~7V Buck Regulator; Part Number: 05.2030.00; Part Type: 降压型DCDC; 供应商: ETA; 联系人: 徐卓荣; 手机: 13923780263; 邮箱: xuzhuorong@etasolution.com; Datasheet: ETA3416 V1.4.pdf
U3 = SY8088: ETA ETA3409 2A 3MHz Input-2.6V~5.5V Buck Regulator; Part Number: 05.2016.00; Part Type: 降压型DCDC; 供应商: ETA; 联系人: 徐卓荣; 手机: 13923780263; 邮箱: xuzhuorong@etasolution.com; Datasheet: ETA3409_V1.2.pdf
C29 C37 C40 C45 C62 C63 = CAP: Capacitor-10uF,+/-20%,X5R,6.3V-0402+; Part Number: 02.0034.00; Part Type: 0402表贴普通电容; 供应商: 国巨 / Murata; 规格型号1: CC0402MRX5R5BB106 / GRM155R60J106ME44D; 联系人: 谢苏云; 手机: 15900554174; 邮箱: susan.xie@murata.com
C30 C31 C41 = CAP: Capacitor-10uF,+/-20%,X5R,6.3V-0402+; Part Number: 02.0034.00; Part Type: 0402表贴普通电容; 供应商: YAGEO / Murata; 规格型号1: CC0402MRX5R5BB106 / GRM155R60J106ME44D; 联系人: 谢苏云; 手机: 15900554174; 邮箱: susan.xie@murata.com
C36 C38 C39 C44 C49 = CAP: Capacitor-10nF,+/-10%,X7R,6.3V-0402; Part Number: 02.0075.00; Part Type: 0402表贴普通电容; 供应商: Murata; 规格型号1: GRM155R70J102KA01D; 联系人: 谢苏云; 手机: 15900554174; 邮箱: susan.xie@murata.com
C51 C53 C55 C71 C73 C76 C78 C91 C93 C99 C100 = CAP: Capacitor-1uF,+/-10%,X7R,6.3V-0402; Part Number: 02.0076.00; Part Type: 0402表贴普通电容; 供应商: Murata; 规格型号1: GRM155R70J105KA12; 联系人: 谢苏云; 手机: 15900554174; 邮箱: susan.xie@murata.com
FB1-FB7 FB9 FB10 = BEAD: Murata BLM15HG102SN1D Z=1000ohm@100MHz 250mA 1.1ohm 25%; Part Number: 03.1001.00; Part Type: 0402表贴磁珠; 供应商: Murata; 规格型号1: BLM15HG102SN1D; 联系人: 谢苏云; 手机: 15900554174; 邮箱: susan.xie@murata.com; Datasheet: BLM15HG.pdf
R17 R18 R24 R28 R44 R63 R64 R73 R80 R84 R294 R323-R331 = RES: Resistor-0R,+/-5%,1/10W-0603; Part Number: 01.0051.00; Part Type: 0603表贴普通电阻; 供应商: 厚声; 规格型号1: 0603WAJ0000T5E
R19 R22 R25 R41 R42 = RES: Resistor-10K,+/-1%,1/16W-0402; Part Number: 01.0024.00; Part Type: 0402表贴高精度电阻; 供应商: 厚声; 规格型号1: 0402WGF1002TCE
R20 R21 = RES: Resistor-240R,+/-1%,1/16W-0402; Part Number: 01.0010.00; Part Type: 0402表贴高精度电阻; 供应商: 厚声; 规格型号1: 0402WGF2400TCE
BT1 = BATTERY: 2.54mm Pitch 2P LC PTH Connector; Part Number: 04.0036.00; Part Type: 2.54mm立插电池座; 规格型号1: 2.54mm立插2P
C57 C58 = CAP: Capacitor-18pF,+/-2%,C0G,50V-0402; Part Number: 02.0049.00; Part Type: 0402表贴普通电容; 供应商: YAGEO / Murata; 规格型号1: CC0402GRNPO9BN180 / GRM1555C1H180GA01D; 联系人: 谢苏云; 手机: 15900554174; 邮箱: susan.xie@murata.com
C64 C68 C75 C85 = CAP: Capacitor-4.7uF,+/-20%,X5R,6.3V-0402; Part Number: 02.0018.00; Part Type: 0402表贴普通电容; 供应商: 国巨 / Murata; 规格型号1: CC0402MRX5R5BB475 / GRM153R60J475ME15D; 联系人: 谢苏云; 手机: 15900554174; 邮箱: susan.xie@murata.com
C69 C70 = CAP: Capacitor-12pF,+/-5%,C0G,50V-0402; ID: 8; Part Number: 02.0006.00; Part Type: 0402表贴普通电容; 供应商: 国巨 / Murata; 供应商2: Murata; 规格型号1: CC0402JRNPO9BN120 / GCM1555C1H120JA16D; 联系人: 谢苏云; 联系人2: 吴铭; 手机: 15900554174; 手机2: 13761466262; 邮箱: susan.xie@murata.com; 邮箱2: cherry.wu@murata.com
C80 = CAP: Capacitor-1uF,+/-10%,X5R,10V-0402; Part Number: 02.0016.00; Part Type: 0402表贴普通电容; 供应商: Murata; 规格型号1: GRT155R61A105KE01D; 联系人: 谢苏云; 手机: 15900554174; 邮箱: susan.xie@murata.com
D3 D5 = ESD: Murata LXES15AAA1-153 Bidirection 0.05pF ESD Protection Device; Part Number: 09.0015.00; 供应商: Murata; 规格型号1: LXES15AAA1-153; 联系人: 吴铭; 手机: 13761466262; 邮箱: cherry.wu@murata.com; Datasheet: LXES15AAA1-153.pdf
D4 = ESD: WILL ESD5451X-2/TR Bidirection 17.5pF Transient Voltage Suppressor; Part Number: 09.0006.00; 供应商: Will; 规格型号1: ESD5451X-2/TR; 联系人: 安志鹏; 手机: 18321800431; 邮箱: an.zhipeng@sh-willsemi.com; Datasheet: ESD5451X.pdf
FB8 = BEAD: Murata BLM15PX221SN1D Z=220ohm@100MHz 1.4A 0.1ohm 25%; Part Number: 03.1006.00; Part Type: 0402表贴磁珠; 供应商: Murata; 规格型号1: BLM15PX221SN1D; 联系人: 谢苏云; 手机: 15900554174; 邮箱: susan.xie@murata.com; Datasheet: BLM15.pdf
J7 = MICROUSB_0: USB Connector  MICRO USB 带牛角有卷边无柱; Part Number: 04.0023.00; Part Type: USB连接器; 供应商: 深圳旺科达; 规格型号1: MicroB USB母座; 联系人: 童国相; 手机: 13824380089; 邮箱: wangkeda2008@163.com; Datasheet: MICRO USB 带牛角有卷边无柱.pdf
Q1 = PHOTO_DIODE: 鑫永诚 PHOTO_DIODE PT550 series VCC=5V; Part Number: 07.1011.00; Part Type: 光敏; 供应商: 鑫永诚; Datasheet: XYC-PT5E550BC-IC.pdf
R23 R31 = RES: Resistor-1M,+/-5%,1/16W-0402; ID: 49; Part Number: 01.0049.00; Part Type: 0402表贴普通电阻; 供应商: 厚声; 供应商1: Eyang; 规格型号1: 0402WGJ0105TCE; 联系人1: 何俊; 手机1: 18317187178; 邮箱1: hejunxs@szeyang.com
R32 = RES: Resistor-33R,+/-5%,1/16W-0402; ID: 18; Part Number: 01.0005.00; Part Type: 0402表贴普通电阻; 供应商: 厚声; 供应商1: Eyang; 规格型号1: 0402WGJ0330TCE; 联系人1: 何俊; 手机1: 18317187178; 邮箱1: hejunxs@szeyang.com
R34 R37 R46 R48 R49 R51 R54 R55 R67 R68 R72 R75 R76 R79 R81-R83 R85-R88 R120 R121 R123 R124 R153 R156 R165 R167 R229 R287 R309 R311 R318-R322 = RES: Resistor-0R,+/-5%,1/16W-0402; Part Number: 01.0001.00; Part Type: 0402表贴普通电阻; 供应商: 厚声; 规格型号1: 0402WGJ0000TCE
R36 = LDR: Part Number: 07.1006.00; Part Type: Other Sensor
R39 = RES_KT: Resistor-1M,+/-10%,1/2W Adjustable; Part Number: 01.0083.00; Part Type: 3296W可调电阻
R151 R152 = RES: Resistor-2.2R,+/-1%,1/16W-0402; Part Number: 01.0126.00; Part Type: 0402表贴高精度电阻; 供应商: 厚声; 规格型号1: 0402WGF220KTCE
R241 = RES: Resistor-13K,+/-5%,1/16W-0402; Part Number: 01.0037.00; Part Type: 0402表贴普通电阻; 供应商: 厚声; 规格型号1: 0402WGJ0133TCE
R243 R280 R283 R284 = RES: Resistor-4.7R,+/-5%,1/16W-0402; Part Number: 01.0126.00; Part Type: 0402表贴普通电阻; 供应商: 厚声; 规格型号1: 0402WGJ470TCE
R310 = RES: Resistor-15K,+/-1%,1/16W-0402; Part Number: 01.0024.00; Part Type: 0402表贴高精度电阻; 供应商: 厚声; 规格型号1: 0402WGF1502TCE
SW1 = SW_5: PUSHBUTTON 10mmX6mm 5Pin; Part Number: 04.1002.00; Part Type: 按键; 规格型号1: 6*6*3.1-5P轻触按键
TP12 TP13 = TP: SMD Test Point φ0.5mm; Part Number: AA.0006.00; Part Type: Test Point
U6 = T41_BGA232: Ingenic T41 Smart Video Processor FBGA 232Ball 0.65mmPitch 11mmX11mm; Part Number: 06.0137.00; Part Type: CPU; 供应商: Ingenic; 规格型号1: T41; 11: 3.3V
U7 U28 = SPI_NOR: Giga Device GD25Q127CSIG 128Mbit SPI NOR FLASH MEMORY; Part Number: 06.0118.00; Part Type: SPI NOR; 供应商: 兆易创新; 联系人: 薛霆; 手机: 13910816516; 邮箱: ting.xue@gigadevice.com; Datasheet: GD25Q127C_Rev1.0.pdf
U8 = SGM810: SGMICRO SGM809-XXN3 1.63V THRESHOLD Microprocessor Supervisory Circuit; Part Number: 06.0109.00; Part Type: 复位芯片; 供应商: SGM; 规格型号1: SGM809-XXN3/TR; 联系人: 高晓英; 手机: 13501190893; 邮箱: glarie_gao@sg-micro.com; Datasheet: SGM810.pdf
U9 = SGM2554A: SGMICRO SGM2554A Power Distribution Switch; Part Number: 06.0057.00; Part Type: 电源开关芯片; 供应商: SGM; 规格型号1: SGM2554AYN5G/TR; 联系人: 高晓英; 手机: 13501190893; 邮箱: glarie_gao@sg-micro.com; Datasheet: SGM2554 REV.A_20130503.pdf
Y1 = XTAL_P2: MICRO Crystal CM7V-T1A Crystal 32.768KHz 12.5pF; Part Number: 08.0016.00; Part Type: Crystal; 供应商: MicroCrystal; 规格型号1: CM7V-T1A; 联系人: 郑蓓蓓; 手机: 13482156565; 邮箱: Sherry.Zheng@cn.swatchgroup.com; Datasheet: CM7V-T1A.pdf
Y2 = XTAL_P4: Murata XRCGB24M000F2P01R0 Crystal initial ±20ppm 8pF; Part Number: 08.0001.00; Part Type: Crystal; 供应商: Murata; 规格型号1: XRCGB24M000F2P01R0; 联系人: 谢苏云; 手机: 15900554174; 邮箱: susan.xie@murata.com; Datasheet: XRCGB24M000F2P01R0.pdf
R43 R45 R47 R50 R52 R53 R65 R66 R69-R71 R74 R77 = RES: Resistor-33R,+/-5%,1/16W-0402; Part Number: 01.0005.00; Part Type: 0402表贴普通电阻; 供应商: 厚声; 规格型号1: 0402WGJ0330TCE
R62 = RES: Resistor-2.49K,+/-1%,1/16W-0402; Part Number: 01.0134.00; Part Type: 0402表贴高精度电阻; 供应商: 厚声; 规格型号1: 0402WGF2491TCE
C190 = CAP: Capacitor-4.7uF,+/-20%,X5R,6.3V-0402; Part Number: 02.0018.00; Part Type: 0402表贴普通电容; 供应商: YAGEO / Murata; 规格型号1: CC0402MRX5R5BB475 / GRM153R60J475ME15D; 联系人: 谢苏云; 手机: 15900554174; 邮箱: susan.xie@murata.com

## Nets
12V_IN: F1.1 J2.3
AVDDL_REG: C98.1 C99.1 U6.R16(AVDDL_REG)
DVDD1V2OUT: C97.1 C100.1 U6.T14(DVDD1V2OUT)
GND: BT1.2(-) C2.2 C3.2 C4.2 C5.2 C6.2 C8.2 C9.2 C10.2 C11.2 C12.2 C14.2 C16.2 C17.1 C18.2 C19.2 C21.2 C22.2 C23.2 C25.2 C26.2 C27.2 C28.2 C29.2 C30.2 C31.2 C32.2 C33.2 C34.2 C35.2 C36.2 C37.2 C38.2 C39.2 C40.2 C41.2 C42.2 C43.2 C44.2 C45.2 C46.2 C47.2 C48.2 C49.2 C51.2 C52.2 C53.2 C54.2 C55.2 C56.2 C57.1 C58.1 C59.1 C60.2 C61.2 C62.2 C63.2 C64.2 C67.2 C68.2 C69.1 C70.1 C71.2 C72.2 C73.2 C74.2 C75.2 C76.2 C77.2 C78.2 C79.2 C80.2 C81.2 C82.2 C83.2 C84.2 C85.2 C86.2 C87.2 C88.2 C89.2 C90.2 C91.2 C92.2 C93.2 C94.2 C95.2 C96.2 C97.2 C98.2 C99.2 C100.2 C101.2 C102.2 C103.2 C190.2 C191.1 C192.1 D1.1 D2.2(CATHODE) D3.1(ANODE) D4.1(ANODE) D5.1(ANODE) J1.1 J1.2 J7.5(GND1) J7.6(GND2) J7.7(GND3) J7.8(GND4) J7.9(GND5) J7.10(GND6) J7.11(GND7) R3.1 R8.1 R9.1 R14.1 R15.1 R20.1 R21.1 R22.1 R29.1 R38.1 R39.3 R40.1 R41.1 R42.1 R59.2 R61.2 R62.2 R310.2 SW1.2 SW1.3 SW1.4 U1.2(GND) U2.2(GND) U3.2(GND) U4.2(GND) U5.2(GND) U6.C9(DDRPLL_VSSA) U6.G5(PLL_AVSS) U6.G6(VSS1) U6.G7(VSS2) U6.G8(VSS3) U6.G9(VSS4) U6.G10(VSS5) U6.G11(VSS6) U6.G12(VSS7) U6.G13(VSS8) U6.J6(VSS9) U6.J7(VSS10) U6.J8(VSS11) U6.J9(VSS12) U6.J10(VSS13) U6.J11(VSS14) U6.J12(VSS15) U6.K6(VSS16) U6.K7(VSS17) U6.K8(VSS18) U6.K9(VSS19) U6.K10(VSS20) U6.K11(VSS21) U6.K12(VSS22) U6.L6(VSS23) U6.L7(VSS24) U6.L8(VSS25) U6.L9(VSS26) U6.L10(VSS27) U6.L11(VSS28) U6.L12(VSS29) U6.M7(VSS30) U6.M8(VSS31) U6.M9(VSS32) U6.M10(VSS33) U6.M11(VSS34) U6.M12(VSS35) U6.M13(VSS36) U6.N5(CSI_VSSA) U6.N12(VSS37) U6.N13(SADC_AGND) U6.P4(CODEC_AVSS) U7.4(GND) U8.1(GND) U9.2(GND) U28.4(GND) Y2.2 Y2.4 ; also on sheet 8 9 10 11 12 13 14 15
VBUS_5V: C81.1 C82.1 D4.2(CATHODE) FB8.1 J7.1(VBUS) J8.2
VCC_1V8: C24.1 C27.1 J6.1 L5.2 Q1.1(BASE) R13.2 R30.1 R33.1 R36.1 R37.2 U8.3(VCC) ; also on sheet 15
VCC_3V3: C13.1 C18.1 J3.1 L2.2 R7.2 R24.2 R73.2 ; also on sheet 8 9 10 11 12 13 14 15
VCC_5V: C7.1 C8.1 C9.1 C10.1 C11.1 C14.1 C21.1 C25.1 C80.1 J8.1 L1.2 R2.1 R4.1 R5.1 R10.1 R11.1 R25.2 TP1.1 U2.4(IN) U3.4(IN) U4.4(IN) U5.4(IN) U9.3(VIN) ; also on sheet 8 9 11 12 14
VCC_12V: C2.1 C3.1 C4.1 C5.1 D1.2 F1.2 R1.1 TP2.1 U1.5(VIN)
VCC_BAT: BT1.1(+) R35.2
VCC_DDR: C20.1 C23.1 J5.1 L4.2 R12.2
VDD_RTC: C59.2 R294.1 U6.L15(VDD_RTC)
VDDIO18: C192.2 R28.1 U6.N11(VDDIO18_1)
VDDIO18_DVP: C95.1 R44.2 U6.K2(VDDIO18_2)
VDDIO33_1: C101.1 R64.1 U6.C4(VDDIO2)
VDDIO33_2: C102.1 C103.1 R63.1 U6.J14(VDDIO1_2) U6.P9(VDDIO1_1)
VDDIO_RTC: C191.2 R323.1 U6.L17(VDDIO_RTC)
VDDMEM: C40.1 C41.1 C42.1 C43.1 C44.1 R17.2 U6.E6(VDDMEM1) U6.E7(VDDMEM2) U6.E8(VDDMEM3) U6.E9(VDDMEM4) U6.E10(VDDMEM5) U6.E11(VDDMEM6) U6.E12(VDDMEM7)
ADC0: C87.1 R35.1 R40.2 R243.2 TP14.1
ADC1: C88.1 R36.2 R41.2 R280.2 TP17.1
ADC2: C89.1 Q1.2(EMITTER) R42.2 R283.2 TP15.1
ADC3: C90.1 R39.2 R284.2 TP16.1
ADC_AVDD: C71.1 C72.1 FB7.2 U6.N16(SADC_VREFP) U6.N17(SADC_AVDD)
AK7755_PDN: R83.1 ; also on sheet 11
BOOTSEL0: U6.A9(BOOT_SEL0_PC00) ; also on sheet 15
BOOTSEL1: U6.B9(BOOT_SEL1_PC01) ; also on sheet 15
CODEC_AVDD: C61.1 C62.1 FB6.2 U6.R1(CODEC_AVDD)
CORE_0V8: C29.1 C30.1 C31.1 C32.1 C33.1 C34.1 C35.1 C36.1 C37.1 C38.1 C39.1 J4.2 TP4.1 U6.H5(VDD1) U6.H6(VDD2) U6.H7(VDD3) U6.H8(VDD4) U6.H9(VDD5) U6.H10(VDD6) U6.H11(VDD7) U6.H12(VDD8) U6.H13(VDD9) U6.J5(VDD10) U6.J13(VDD11) U6.K5(VDD12) U6.K13(VDD13) U6.L5(VDD14) U6.M5(VDD15) U6.M6(VDD16) U6.N6(VDD17) U6.N7(VDD18) U6.N8(VDD19) U6.N9(VDD20) U6.N10(VDD21)
CSI_CLKN_DVP_D4: U6.M2(CSI_CLKN_DVP_D4) ; also on sheet 9
CSI_CLKP_DVP_D5: U6.L3(CSI_CLKP_DVP_D5) ; also on sheet 9
CSI_DATAN0_DVP_D0: U6.L2(CSI_DATAN0_DVP_D0) ; also on sheet 9
CSI_DATAN1_DVP_D2: U6.N1(CSI_DATAN1_DVP_D2) ; also on sheet 9
CSI_DATAP0_DVP_D1: U6.L1(CSI_DATAP0_DVP_D1) ; also on sheet 9
CSI_DATAP1_DVP_D3: U6.M3(CSI_DATAP1_DVP_D3) ; also on sheet 9
CSI_VCC08: C91.1 C92.1 FB9.1 U6.N2(CSI_VCCA08)
CSI_VCC18: C93.1 C94.1 FB10.1 U6.K3(CSI_VCCA18)
DC_12V: J1.3 J2.2
DDR_VREF: C50.2 C54.1 R19.1 R22.2 U6.E5(DDR_VREF)
DDRPLL_VCCA: C51.1 C52.1 FB1.2 U6.B8(DDRPLL_VCCA)
DDRVDD: C45.1 C46.1 C47.1 C48.1 C49.1 C50.1 C53.1 R18.2 R19.2 U6.F5(DDRVDD1) U6.F6(DDRVDD2) U6.F7(DDRVDD3) U6.F8(DDRVDD4) U6.F9(DDRVDD5) U6.F10(DDRVDD6) U6.F11(DDRVDD7) U6.F12(DDRVDD8)
DMIC_CLK_PB28: R153.2 ; also on sheet 10
DMIC_DAT0_PB29: R321.2 ; also on sheet 10
DMIC_DAT1_PB30: R322.2 ; also on sheet 10
DRV_VBUS: R38.2 R55.2 U9.4(EN)
DVP_D6: U6.H2(SD0_DVP_D6_PA06) ; also on sheet 9
DVP_D7: U6.H3(SD1_DVP_D7_PA07) ; also on sheet 9
DVP_D8: U6.G1(SD2_DVP_D8_PA08) ; also on sheet 9
DVP_D9: U6.G2(SD3_DVP_D9_PA09) ; also on sheet 9
DVP_HSYNC: U6.J2(CS2_DVP_HSYNC_PA16) ; also on sheet 9
DVP_PCLK: U6.F3(SA0_DVP_PCLK__PA14) ; also on sheet 9
DVP_VSYNC: U6.J3(RD_DVP_VSYNC_PA17) ; also on sheet 9
EC_CLK: R45.2 R65.2 U6.A1(MSC1_CLK_PC02)
EC_CMD: R66.2 R309.1 U6.C3(MSC1_CMD_PC03)
EC_D0: R69.2 R311.1 U6.B2(MSC1_D0_PC04)
EC_D1: R70.2 R318.1 U6.A2(MSC1_D1_PC05)
EC_D2: R71.2 R319.1 U6.C2(MSC1_D2_PC06)
EC_D3: R74.2 R320.1 U6.B1(MSC1_D3_PC07)
EFUSE_AVDD: R324.1 U6.D4(EFUSE_AVDD)
EFUSE_AVDD18: R324.2 ; also on sheet 15
EFUSE_EN: R79.1 ; also on sheet 15
EMMC_CLK: R65.1 ; also on sheet 10
EMMC_CMD: R66.1 ; also on sheet 10
EMMC_D0: R69.1 ; also on sheet 10
EMMC_D1: R70.1 ; also on sheet 10
EMMC_D2: R71.1 ; also on sheet 10
EMMC_D3: R74.1 ; also on sheet 10
EMMC_RST: R76.2 ; also on sheet 10
EN_DLDO: R60.1 R61.1 U6.U15(EN_DLDO)
EXCLKI: C69.2 R31.2 U6.C1(EXCLK_XIN) Y2.1
EXCLKO: R31.1 R32.2 U6.D2(EXCLK_XOUT)
GMAC_MDC: R49.2 ; also on sheet 13
GMAC_MDIO: R51.2 ; also on sheet 13
GMAC_NRST_PB28: R156.1 R287.2 ; also on sheet 13
GMAC_PHY_CLK: R47.2 ; also on sheet 13
GMAC_RXD0: U6.U13(GMAC_RXD0_PWM6_PB15) ; also on sheet 13
GMAC_RXD1: U6.R12(GMAC_RXD1_PWM7_PB16) ; also on sheet 13
GMAC_RXDV: U6.U9(GMAC_RXDV_PWM3_PB09) ; also on sheet 13
GMAC_TXCLK: U6.T12(GMAC_TXCLK_PB06) ; also on sheet 13
GMAC_TXD0: R52.2 ; also on sheet 13
GMAC_TXD1: R53.2 ; also on sheet 13
GMAC_TXEN: R48.2 ; also on sheet 13
HPOUTL: U6.T1(HPOUTL) ; also on sheet 8
I2C0_MIPI_DVP_SCK: U6.J4(SD7_SMB0_SCK_PA13) ; also on sheet 9
I2C0_MIPI_DVP_SDA: U6.J1(SD6_SMB0_SDA_PA12) ; also on sheet 9
I2C1_SCK_CODEC: R88.1 ; also on sheet 11
I2C1_SCK_RTC: U6.C10(SMB1_SCK_UART3_RXD_PB26) ; also on sheet 15
I2C1_SDA_CODEC: R86.1 ; also on sheet 11
I2C1_SDA_RTC: U6.C11(SMB1_SDA_UART3_TXD_PB25) ; also on sheet 15
I2S_DAC_BCLK: U6.B4(SSI_SLV_CLK_I2S_DAC_BCLK_PC15) ; also on sheet 11
I2S_DAC_LRCK: U6.A3(SSI_SLV_CE0_I2S_DAC_LRCK_PC16) ; also on sheet 11
I2S_DAC_MCLK: R77.1 ; also on sheet 11
I2S_SDTI: U6.B5(SSI_SLV_DR_I2S_SDTI_PC18) ; also on sheet 11
I2S_SDTO: U6.B3(SSI_SLV_DT_I2S_SDTO_PC17) ; also on sheet 11
KEY1_PB19: TP20.1 U6.D16(MSC1_CMD_PB19) ; also on sheet 15
LED0: U6.R13(LED0) ; also on sheet 13
LED1: U6.R15(LED1) ; also on sheet 13
M_RSTB: R72.2 ; also on sheet 12
M_VD_FZ: R75.2 ; also on sheet 12
MICBIAS: C85.1 C86.1 U6.P3(MICBIAS) ; also on sheet 8
MICNL: C66.2 ; also on sheet 8
MICPL: C65.2 ; also on sheet 8
MINNL: C66.1 U6.P2(MICNL)
MINPL: C65.1 U6.N3(MICPL)
MIPI_DVP_IRCUTN_PB18: TP19.1 U6.E17(MSC1_D1_PB18) ; also on sheet 9
MIPI_DVP_IRCUTP_PB17: TP18.1 U6.E16(MSC1_D0_PB17) ; also on sheet 9
MIPI_DVP_MCLK: R50.1 ; also on sheet 9
MIPI_DVP_PWDN_PA19: R229.1 ; also on sheet 9
MIPI_DVP_RESET: U6.E3(SA2_PA18) ; also on sheet 9
MSC0_CLK_PB04: R43.2 ; also on sheet 12
MSC0_CMD_PB05: U6.G17(MSC0_CMD_PB05) ; also on sheet 12
MSC0_D0_PB00: U6.H16(MSC0_D0_PB00) ; also on sheet 12
MSC0_D1_PB01: U6.J15(MSC0_D1_PB01) ; also on sheet 12
MSC0_D2_PB02: U6.G15(MSC0_D2_PB02) ; also on sheet 12
MSC0_D3_PB03: U6.G16(MSC0_D3_PB03) ; also on sheet 12
OSC32_XI: C57.2 R23.2 U6.M16(OSC32_XI) Y1.2
OSC32_XO: C58.2 R23.1 U6.M15(OSC32_XO) Y1.1
PHY_NRST: C96.1 R56.1 R287.1 U6.T13(PHY_RST)
PLL_AVDD18: C55.1 C56.1 FB3.2 U6.D3(PLL_AVDD)
POR_CTRL: R29.2 R30.2 U6.K16(POR_CTL)
PPRST_N: R34.2 U6.L16(PPRST_) U8.2(RESET)
PWRON: TP9.1 U6.K15(PWRON)
RD_N: U6.U17(RD_N) ; also on sheet 13
RD_P: U6.T17(RD_P) ; also on sheet 13
RMII_MDCK: R49.1 U6.R10(GMAC_MDCK_SMB2_SDA_PB10)
RMII_MDIO: R51.1 U6.T10(GMAC_MDIO_SMB2_SCK_PB11)
RMII_PHY_CLK: R47.1 U6.T9(GMAC_PHY_CLK_PB07)
RMII_TX0: R52.1 U6.R11(GMAC_TXD0_PWM4_PB13)
RMII_TX1: R53.1 U6.T11(GMAC_TXD1_PWM5_PB14)
RMII_TXEN: R48.1 U6.U11(GMAC_TXEN_PWM2_PB08)
RST_OUT: TP7.1 U6.J16(RST_OUT)
RTC_0V8: R294.2 ; also on sheet 15
RTC_1V8: R323.2 ; also on sheet 15
RTC_IRQ_N: R46.1 R68.2 ; also on sheet 15
RX_DV: R57.1 U6.P14(RX_DV)
RXD3: R58.1 R59.1 U6.R14(RXD3)
SD0_CD_N_PB27: R54.1 ; also on sheet 12
SD_CLK: R43.1 U6.H15(MSC0_CLK_PB04)
SD_PWR_EN_N: TP21.1 U6.E15(MSC1_CLK_TCK_PB20) ; also on sheet 12
SDIO_WIFI_CLK_PC02: R45.1 ; also on sheet 12
SDIO_WIFI_CMD_PC03: R309.2 ; also on sheet 12
SDIO_WIFI_D0_PC04: R311.2 ; also on sheet 12
SDIO_WIFI_D1_PC05: R318.2 ; also on sheet 12
SDIO_WIFI_D2_PC06: R319.2 ; also on sheet 12
SDIO_WIFI_D3_PC07: R320.2 ; also on sheet 12
SDIO_WIFI_EN_PC09: U6.C6(SMB2_SCK_PC09) ; also on sheet 12
SFC1_CE: R123.1 R124.1 U6.R7(SFC1_CE_PA29)
SFC1_CLK: R120.1 R121.1 U6.T8(SFC1_CLK_PA22)
SFC1_CS_N: R78.1 R124.2 U28.1(~{CS})
SFC1_DR_IO1: R67.1 R87.1 U6.T7(SFC1_DR_IO1_PA21)
SFC1_DT_IO0: R82.1 R85.1 U6.R8(SFC1_DT_IO0_PA20)
SFC1_HD_IO3: R75.1 R165.1 U6.R9(SFC1_HOLD_IO3_PA31)
SFC1_SCLK: R121.2 U28.6(SCLK)
SFC1_SIO0: R85.2 U28.5(SI/SIO0)
SFC1_SIO1: R87.2 U28.2(SO/SIO1)
SFC1_SIO2: R167.2 U28.3(~{WP}/SIO2)
SFC1_SIO3: R165.2 U28.7(~{RESET}/SIO3)
SFC1_WP_IO2: R72.1 R167.1 U6.U7(SFC1_WP_IO2_PA30)
SFC_CS_N: R26.1 U6.T4(SFC0_CE_PA28) U7.1(~{CS})
SFC_SCLK: U6.R6(SFC0_CLK_PA27) U7.6(SCLK)
SFC_SIO0: U6.U5(SFC0_DT_IO0_PA23) U7.5(SI/SIO0)
SFC_SIO1: U6.R5(SFC0_DR_IO1_PA24) U7.2(SO/SIO1)
SFC_SIO2: U6.T5(SFC0_WP_IO2_PA26) U7.3(~{WP}/SIO2)
SFC_SIO3: U6.T6(SFC0_HOLD_IO3_PA25) U7.7(~{RESET}/SIO3)
SLCD_BLEN: R81.1 ; also on sheet 14
SLCD_BT656_D0: U6.A15(SLCD_D0_UART3_TXD_PD00) ; also on sheet 14
SLCD_BT656_D1: U6.B15(SLCD_D1_UART3_RXD_PD01) ; also on sheet 14
SLCD_BT656_D2: U6.A16(SLCD_D2_UART4_TXD_PD02) ; also on sheet 14
SLCD_BT656_D3: U6.C15(SLCD_D3_UART4_RXD_PD03) ; also on sheet 14
SLCD_BT656_D4: U6.A17(SLCD_D4_UART5_TXD_PD04) ; also on sheet 14
SLCD_BT656_D5: U6.B16(SLCD_D5_UART5_RXD_PD05) ; also on sheet 14
SLCD_BT656_D6: U6.B17(SLCD_D6_SMB1_SDA_PD06) ; also on sheet 14
SLCD_BT656_D7: U6.C16(SLCD_D7_SMB1_SCK_PD07) ; also on sheet 14
SLCD_CS: TP27.1 U6.B13(SLCD_CS_PWM5_PD10) ; also on sheet 14
SLCD_DC: TP28.1 U6.C13(SLCD_DC_PWM6_PD11) ; also on sheet 14
SLCD_RDY: TP29.1 U6.C14(SLCD_RDY_PWM7_PD12) ; also on sheet 14
SLCD_TE: TP26.1 U6.A13(SLCD_TE_PWM4_PD09) ; also on sheet 14
SLCD_WR_BT656_PCLK: U6.B14(SLCD_WR_PD08) ; also on sheet 14
SOC_0V8: C15.2 C16.1 C17.2 J4.1 L3.2 R6.2 R325.1 R330.2
SOC_1V8: J6.2 R27.2 R28.2 R44.1 R80.1 R84.1 R326.1 R328.1 R329.1 R331.2 TP6.1
SOC_3V3: J3.2 R16.1 R56.2 R57.2 R58.2 R60.2 R63.2 R64.2 R327.1 TP3.1
SOC_DDR: J5.2 R17.1 R18.1 TP5.1
SPEAK_EN_PB31: U6.B10(GPIO_PB31) ; also on sheet 8 11
SPI1_CLK: R120.2 ; also on sheet 12
SPI1_CS: R123.2 ; also on sheet 12
SPI1_DR: R67.2 ; also on sheet 12
SPI1_DT: R82.2 ; also on sheet 12
TD_N: U6.U16(TD_N) ; also on sheet 13
TD_P: U6.T16(TD_P) ; also on sheet 13
TEST_TE: TP8.1 U6.L13(TEST_TE)
U0_RTS_PB21: R76.1 TP22.1 U6.C17(MSC1_D2_TMS_PB21)
U0_TXD_PB22: R68.1 TP23.1 U6.D15(MSC1_D3_PB22)
UART1_RXD_PB24: U6.F16(UART1_RXD_PB24) ; also on sheet 15
UART1_TXD_PB23: U6.F15(UART1_TXD_PB23) ; also on sheet 15
USB_AVD08: C73.1 C74.1 FB4.2 U6.R4(USB_AVD08)
USB_AVD18: C76.1 C77.1 FB2.2 U6.T3(USB_AVD18)
USB_AVD33: C78.1 C79.1 FB5.2 U6.R3(USB_AVD33)
USB_DM: R151.1 U6.U1(USB0PN)
USB_DP: R152.1 U6.T2(USB0PP)
USB_ID: R27.1 U6.U2(USB0ID)
USB_VBUS: R25.1 R310.1 U6.U3(VBUS)
VCM: C67.1 C68.1 U6.R2(VCM)
WIFI_WAKE_HOST: TP45.1 U6.B6(SMB2_SDA_PC08)
WKUP_PD31: TP11.1 U6.J17(WKUP_PD31)
N14970173: C7.2 R2.2 R3.2 U1.3(FB)
N14970293: C1.2 L1.1 U1.6(LX)
N15664622: C6.1 R1.2 U1.4(EN)
N16749111: C60.1 C64.1 R24.1 R26.2 U7.8(VCC)
N16751575: C70.2 R32.1 Y2.3
N16753264: C75.1 R33.2 R34.1 SW1.1 SW1.5
N16757380: R37.1 R39.1
N16760505: D3.2(CATHODE) J7.2(D-) R151.2 TP13.1
N16760513: D5.2(CATHODE) J7.3(D+) R152.2 TP12.1
N16760739: C83.1 C84.1 FB8.2 U9.1(VOUT0) U9.5(VOUT1)
N16779173: R50.2 U6.E1(SA1_DVP_MCLK_PA15)
N17093743: D2.1(ANODE) R16.2
N17289134: C12.1 R4.2 U2.1(EN)
N17289227: C13.2 R7.1 R8.2 U2.5(FB)
N17289243: L2.1 U2.3(LX)
N17291669: C22.1 R10.2 U4.1(EN)
N17291730: C20.2 R12.1 R14.2 U4.5(FB)
N17291736: L4.1 U4.3(LX)
N17297008: C26.1 R11.2 U5.1(EN)
N17297010: C24.2 R13.1 R15.2 U5.5(FB)
N17297090: L5.1 U5.3(LX)
N17502278: R20.2 U6.F13(DDR_ZQ)
N17525430: C63.1 FB6.1 R328.2
N17525778: FB4.1 R325.2
N17525816: FB2.1 R326.2
N17525850: FB5.1 R327.2
N17560999: FB7.1 R329.2
N17611755: C15.1 R6.1 R9.2 U3.5(FB)
N17611809: C19.1 R5.2 U3.1(EN)
N17611937: L3.1 U3.3(LX)
N17672752: TP10.1 U6.D14(TRST_)
N17678928: R153.1 R156.2 U6.A11(DMIC_CLK_SMB2_SCK_PB28)
N17679213: R54.2 R55.1 U6.B11(DRV_VBUS_SMB2_SDA_PB27)
N17680383: R62.1 U6.T15(RBIAS)
N17689049: R77.2 U6.C5(I2S_DAC_MCLK_PC11)
N17689055: R81.2 U6.B7(I2S_ADC_BCLK_PC13)
N17689058: R83.2 U6.C7(I2S_ADC_LRCK_PC14)
N17690769: R86.2 U6.A7(SMB1_SDA_PC19)
N17690856: R88.2 U6.C8(SMB1_SCK_PC20)
N17728418: R21.2 U6.D9(RZQ)
N17957644: R46.2 R321.1 U6.B12(DMIC_DAT0_UART4_TXD_PB29)
N17957722: R322.1 U6.C12(DMIC_DAT1_UART4_RXD_PB30)
N17960615: R229.2 U6.E2(WAIT_PA19)
N17962213: R79.2 U6.A5(I2S_ADC_MCLK_PC12)
N17974466: FB1.1 R80.2
N17976184: FB3.1 R84.2
N17978297: FB9.2 R330.1
N17978317: FB10.2 R331.1
N18062125: C28.1 C190.1 R73.1 R78.2 U28.8(VCC)
N18176543: R243.1 U6.P15(SADC_VIN0)
N18176576: R280.1 U6.R17(SADC_VIN1)
N18176596: R283.1 U6.P16(SADC_VIN2)
N18176636: R284.1 U6.N15(SADC_VIN3)
N18203286: C1.1 U1.1(BS)

Not connected (* = marked no-connect by the designer): J2 1*; J7 4(ID)*; R241 1 2; U6 F2(NC_2)* G3(NC_1)*

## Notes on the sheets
sheet 1
- RD_T41_MARMOT
- INGENIC
- Schematic Revision 1.2
- Title
- Page
- COVER
- 1
- SYSTEM-ARCHITECTURE
- 2
- POWER-SUPPLY
- 3
- T41_POWER
- 4
- T41_SYS_APeripheral
- 5
- T41_INTERFACE_1
- 6
- T41_INTERFACE_2
- 7
- AUDIO
- 8
- MIPI_DVP_CAMERA
- 9
- EMMC_DMIC
- 10
- I2S_CODEC
- 11
- SD_WIFI_AF_MOTOR
- 12
- ETH_PHY
- 13
- SLCD_BT656_OUT
- 14
- UART_RTC_BOOT_EFUSE_KEY
- 15
- REVISION-HISTORY
- 16
sheet 3
- POWER-SUPPLY
- Note：The jumper in         is used for measuring power consumption
  and can be removed in the product board.
- 12V DC-IN
- 5V/2A
- 0.6V
- VOUT=(1+200K/27K)*0.6=5V
- 3.3V/1.5A
- VCC Core 0.8V/2A
- 0.6V
- 0.6V
- Note: Compatible with LN5058/ETA3486
- VOUT=(1+100K/300K)*0.6=0.8V
- VOUT=(1+150K/33.2K)*0.6=3.3V
- DDR POWER/1.5A
- 1.8V/1.5A
- 0.6V
- 0.6V
- Note: Compatible with LN5058/ETA3486
- VCC_DDR=(1+200K/100K)*0.6=1.8V for DDR2
- Note: Compatible with LN5058/ETA3486
- VCC_DDR=(1+150K/100K)*0.6=1.5V for DDR2L or DDR3
- VOUT=(1+200K/100K)*0.6=1.8V
- VCC_DDR=(1+150K/120K)*0.6=1.35V for DDR3L
- √
- Power light
sheet 4
- T41_POWER
- Note：The 0Ω resistance in         is used for measuring power consumption
  and can be removed in the product board.
sheet 5
- T41_SYS_APeripheral
- Note：The 0Ω resistance in         is used for measuring power consumption
  and can be removed in the product board.
- RTC_CLK
- NOR FLASH
- NC
- NC
- NC
- NC
- POR CTRL
- 0    PPRST
- 1    POR
- CLK
- USB2.0
- RESET
- Decap
- NC
- Note：The jumper in         is used to select VCC_5V or
  SGM2554A to supply power to VBUS_5V.
- ADC
- Close to Micbias Pin(P3)
sheet 6
- T41_INTERFACE_1
- Note：The 0Ω resistance in         is used for measuring power consumption
  and can be removed in the product board.
- PIN
- DVP
- BT656_IN
- DVP_D0
- BT656_D0
- L2
- Silkscreen：PWM0
- L1
- DVP_D1
- BT656_D1
- N1
- DVP_D2
- BT656_D2
- Silkscreen：PWM1
- M3
- DVP_D3
- BT656_D3
- M2
- DVP_D4
- BT656_D4
- L3
- DVP_D5
- BT656_D5
- Silkscreen：U0_RXD
- H2
- DVP_D6
- BT656_D6
- H3
- DVP_D7
- BT656_D7
- Silkscreen：U0_CTS
- F3
- DVP_PCLK
- BT656_PCLK
- Silkscreen：U0_RTS
- Silkscreen：U0_TXD
- NC
- NC
- NC
- NC
- NC
- NC
- NC
sheet 7
- T41_INTERFACE_2
- Note：The 0Ω resistance in          is used for measuring power consumption
  and can be removed in the product board.
- NC
- NC
- NC
- NC
- NC
- NC
- Silkscreen：PWM4
- Silkscreen：PWM5
- NC
- NOR FLASH
- Silkscreen：PWM6
- NC
- Silkscreen：PWM7
- NC
- NC
- NC
- NC
- NC
